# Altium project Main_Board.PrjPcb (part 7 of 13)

## Sheet RAM_Power.SchDoc: RAM_POWER
size A3; Organization: Altium Limited; Address1: L3, 12a Rodborough Rd; Address2: Frenchs Forest; Address3: NSW; Address4: Australia 2086
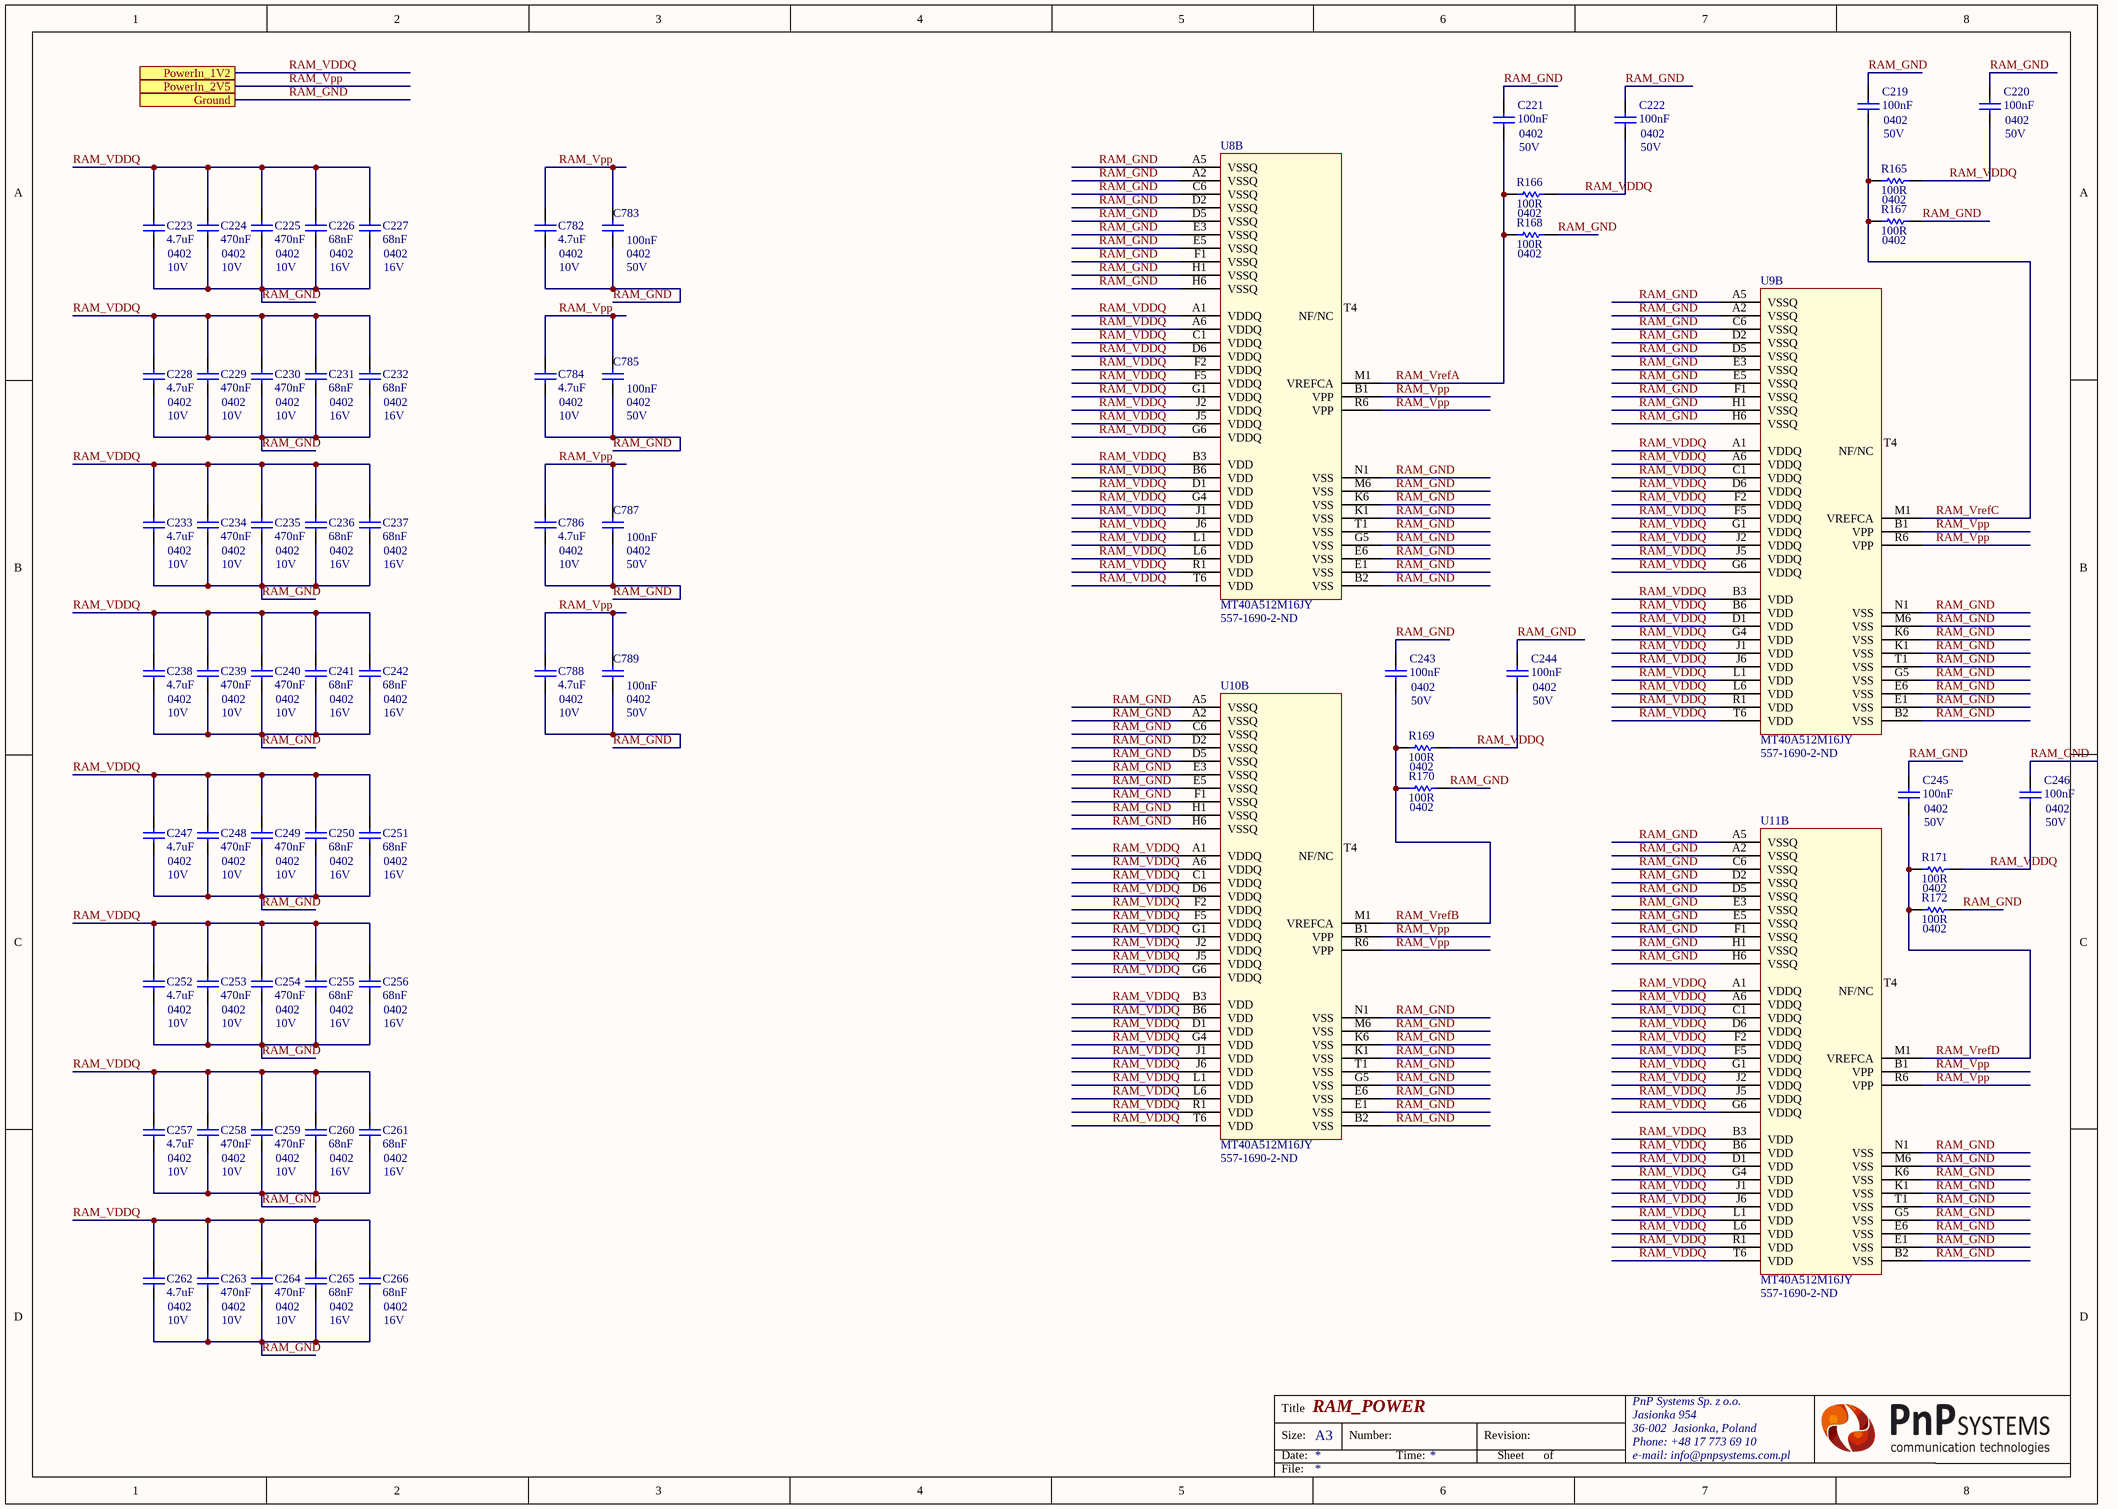
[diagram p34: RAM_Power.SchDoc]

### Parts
C219  100nF  Case Code (Imperial): 0402  Voltage: 50V  [CAP 0402/1005 KK]
C220  100nF  Case Code (Imperial): 0402  Voltage: 50V  [CAP 0402/1005 KK]
C221  100nF  Case Code (Imperial): 0402  Voltage: 50V  [CAP 0402/1005 KK]
C222  100nF  Case Code (Imperial): 0402  Voltage: 50V  [CAP 0402/1005 KK]
C223  4.7uF  Case/Package: 0402  Voltage Rating: 10V  [CAP 0402/1005 KK]
C224  470nF  Case/Package: 0402  Voltage Rating: 10V  [CAP 0402/1005 KK]
C225  470nF  Case/Package: 0402  Voltage Rating: 10V  [CAP 0402/1005 KK]
C226  68nF  Case/Package: 0402  Voltage Rating (DC): 16V  [CAP 0402/1005 KK]
C227  68nF  Case/Package: 0402  Voltage: 16V  [CAP 0402/1005 KK]
C228  4.7uF  Case/Package: 0402  Voltage Rating: 10V  [CAP 0402/1005 KK]
C229  470nF  Case/Package: 0402  Voltage Rating: 10V  [CAP 0402/1005 KK]
C230  470nF  Case/Package: 0402  Voltage Rating: 10V  [CAP 0402/1005 KK]
C231  68nF  Case/Package: 0402  Voltage Rating (DC): 16V  [CAP 0402/1005 KK]
C232  68nF  Case/Package: 0402  Voltage: 16V  [CAP 0402/1005 KK]
C233  4.7uF  Case/Package: 0402  Voltage Rating: 10V  [CAP 0402/1005 KK]
C234  470nF  Case/Package: 0402  Voltage Rating: 10V  [CAP 0402/1005 KK]
C235  470nF  Case/Package: 0402  Voltage Rating: 10V  [CAP 0402/1005 KK]
C236  68nF  Case/Package: 0402  Voltage Rating (DC): 16V  [CAP 0402/1005 KK]
C237  68nF  Case/Package: 0402  Voltage: 16V  [CAP 0402/1005 KK]
C238  4.7uF  Case/Package: 0402  Voltage Rating: 10V  [CAP 0402/1005 KK]
C239  470nF  Case/Package: 0402  Voltage Rating: 10V  [CAP 0402/1005 KK]
C240  470nF  Case/Package: 0402  Voltage Rating: 10V  [CAP 0402/1005 KK]
C241  68nF  Case/Package: 0402  Voltage Rating (DC): 16V  [CAP 0402/1005 KK]
C242  68nF  Case/Package: 0402  Voltage: 16V  [CAP 0402/1005 KK]
C243  100nF  Case Code (Imperial): 0402  Voltage: 50V  [CAP 0402/1005 KK]
C244  100nF  Case Code (Imperial): 0402  Voltage: 50V  [CAP 0402/1005 KK]
C245  100nF  Case Code (Imperial): 0402  Voltage: 50V  [CAP 0402/1005 KK]
C246  100nF  Case Code (Imperial): 0402  Voltage: 50V  [CAP 0402/1005 KK]
C247  4.7uF  Case/Package: 0402  Voltage Rating: 10V  [CAP 0402/1005 KK]
C248  470nF  Case/Package: 0402  Voltage Rating: 10V  [CAP 0402/1005 KK]
C249  470nF  Case/Package: 0402  Voltage Rating: 10V  [CAP 0402/1005 KK]
C250  68nF  Case/Package: 0402  Voltage Rating (DC): 16V  [CAP 0402/1005 KK]
C251  68nF  Case/Package: 0402  Voltage: 16V  [CAP 0402/1005 KK]
C252  4.7uF  Case/Package: 0402  Voltage Rating: 10V  [CAP 0402/1005 KK]
C253  470nF  Case/Package: 0402  Voltage Rating: 10V  [CAP 0402/1005 KK]
C254  470nF  Case/Package: 0402  Voltage Rating: 10V  [CAP 0402/1005 KK]
C255  68nF  Case/Package: 0402  Voltage Rating (DC): 16V  [CAP 0402/1005 KK]
C256  68nF  Case/Package: 0402  Voltage: 16V  [CAP 0402/1005 KK]
C257  4.7uF  Case/Package: 0402  Voltage Rating: 10V  [CAP 0402/1005 KK]
C258  470nF  Case/Package: 0402  Voltage Rating: 10V  [CAP 0402/1005 KK]
C259  470nF  Case/Package: 0402  Voltage Rating: 10V  [CAP 0402/1005 KK]
C260  68nF  Case/Package: 0402  Voltage Rating (DC): 16V  [CAP 0402/1005 KK]
C261  68nF  Case/Package: 0402  Voltage: 16V  [CAP 0402/1005 KK]
C262  4.7uF  Case/Package: 0402  Voltage Rating: 10V  [CAP 0402/1005 KK]
C263  470nF  Case/Package: 0402  Voltage Rating: 10V  [CAP 0402/1005 KK]
C264  470nF  Case/Package: 0402  Voltage Rating: 10V  [CAP 0402/1005 KK]
C265  68nF  Case/Package: 0402  Voltage Rating (DC): 16V  [CAP 0402/1005 KK]
C266  68nF  Case/Package: 0402  Voltage: 16V  [CAP 0402/1005 KK]
C782  4.7uF  Case/Package: 0402  Voltage Rating: 10V  [CAP 0402/1005 KK]
C783  100nF  Case Code (Imperial): 0402  Voltage: 50V  [CAP 0402/1005 KK]
C784  4.7uF  Case/Package: 0402  Voltage Rating: 10V  [CAP 0402/1005 KK]
C785  100nF  Case Code (Imperial): 0402  Voltage: 50V  [CAP 0402/1005 KK]
C786  4.7uF  Case/Package: 0402  Voltage Rating: 10V  [CAP 0402/1005 KK]
C787  100nF  Case Code (Imperial): 0402  Voltage: 50V  [CAP 0402/1005 KK]
C788  4.7uF  Case/Package: 0402  Voltage Rating: 10V  [CAP 0402/1005 KK]
C789  100nF  Case Code (Imperial): 0402  Voltage: 50V  [CAP 0402/1005 KK]
R165  100R  Case/Package: 0402  [RES 0402/1005 RF KK]
R166  100R  Case/Package: 0402  [RES 0402/1005 RF KK]
R167  100R  Case/Package: 0402  [RES 0402/1005 RF KK]
R168  100R  Case/Package: 0402  [RES 0402/1005 RF KK]
R169  100R  Case/Package: 0402  [RES 0402/1005 RF KK]
R170  100R  Case/Package: 0402  [RES 0402/1005 RF KK]
R171  100R  Case/Package: 0402  [RES 0402/1005 RF KK]
R172  100R  Case/Package: 0402  [RES 0402/1005 RF KK]
U8  MT40A512M16JY  Supplier Part Number 1: 557-1690-2-ND  [MT40A512M16JY]  (part B of 2)
U9  MT40A512M16JY  Supplier Part Number 1: 557-1690-2-ND  [MT40A512M16JY]  (part B of 2)
U10  MT40A512M16JY  Supplier Part Number 1: 557-1690-2-ND  [MT40A512M16JY]  (part B of 2)
U11  MT40A512M16JY  Supplier Part Number 1: 557-1690-2-ND  [MT40A512M16JY]  (part B of 2)

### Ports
Ground, PowerIn_1V2, PowerIn_2V5

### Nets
RAM_GND: C219.2 C220.2 C221.2 C222.2 C223.1 C224.1 C225.1 C226.1 C227.1 C228.1 C229.1 C230.1 C231.1 C232.1 C233.1 C234.1 C235.1 C236.1 C237.1 C238.1 C239.1 C240.1 C241.1 C242.1 C243.2 C244.2 C245.2 C246.2 C247.1 C248.1 C249.1 C250.1 C251.1 C252.1 C253.1 C254.1 C255.1 C256.1 C257.1 C258.1 C259.1 C260.1 C261.1 C262.1 C263.1 C264.1 C265.1 C266.1 C782.1 C783.1 C784.1 C785.1 C786.1 C787.1 C788.1 C789.1 R167.2 R168.2 R170.2 R172.2 U8.A2(VSSQ) U8.A5(VSSQ) U8.B2(VSS) U8.C6(VSSQ) U8.D2(VSSQ) U8.D5(VSSQ) U8.E1(VSS) U8.E3(VSSQ) U8.E5(VSSQ) U8.E6(VSS) U8.F1(VSSQ) U8.G5(VSS) U8.H1(VSSQ) U8.H6(VSSQ) U8.K1(VSS) U8.K6(VSS) U8.M6(VSS) U8.N1(VSS) U8.T1(VSS) U9.A2(VSSQ) U9.A5(VSSQ) U9.B2(VSS) U9.C6(VSSQ) U9.D2(VSSQ) U9.D5(VSSQ) U9.E1(VSS) U9.E3(VSSQ) U9.E5(VSSQ) U9.E6(VSS) U9.F1(VSSQ) U9.G5(VSS) U9.H1(VSSQ) U9.H6(VSSQ) U9.K1(VSS) U9.K6(VSS) U9.M6(VSS) U9.N1(VSS) U9.T1(VSS) U10.A2(VSSQ) U10.A5(VSSQ) U10.B2(VSS) U10.C6(VSSQ) U10.D2(VSSQ) U10.D5(VSSQ) U10.E1(VSS) U10.E3(VSSQ) U10.E5(VSSQ) U10.E6(VSS) U10.F1(VSSQ) U10.G5(VSS) U10.H1(VSSQ) U10.H6(VSSQ) U10.K1(VSS) U10.K6(VSS) U10.M6(VSS) U10.N1(VSS) U10.T1(VSS) U11.A2(VSSQ) U11.A5(VSSQ) U11.B2(VSS) U11.C6(VSSQ) U11.D2(VSSQ) U11.D5(VSSQ) U11.E1(VSS) U11.E3(VSSQ) U11.E5(VSSQ) U11.E6(VSS) U11.F1(VSSQ) U11.G5(VSS) U11.H1(VSSQ) U11.H6(VSSQ) U11.K1(VSS) U11.K6(VSS) U11.M6(VSS) U11.N1(VSS) U11.T1(VSS) ; port Ground  [project net B503_Ground]
RAM_VDDQ: C220.1 C222.1 C223.2 C224.2 C225.2 C226.2 C227.2 C228.2 C229.2 C230.2 C231.2 C232.2 C233.2 C234.2 C235.2 C236.2 C237.2 C238.2 C239.2 C240.2 C241.2 C242.2 C244.1 C246.1 C247.2 C248.2 C249.2 C250.2 C251.2 C252.2 C253.2 C254.2 C255.2 C256.2 C257.2 C258.2 C259.2 C260.2 C261.2 C262.2 C263.2 C264.2 C265.2 C266.2 R165.2 R166.2 R169.2 R171.2 U8.A1(VDDQ) U8.A6(VDDQ) U8.B3(VDD) U8.B6(VDD) U8.C1(VDDQ) U8.D1(VDD) U8.D6(VDDQ) U8.F2(VDDQ) U8.F5(VDDQ) U8.G1(VDDQ) U8.G4(VDD) U8.G6(VDDQ) U8.J1(VDD) U8.J2(VDDQ) U8.J5(VDDQ) U8.J6(VDD) U8.L1(VDD) U8.L6(VDD) U8.R1(VDD) U8.T6(VDD) U9.A1(VDDQ) U9.A6(VDDQ) U9.B3(VDD) U9.B6(VDD) U9.C1(VDDQ) U9.D1(VDD) U9.D6(VDDQ) U9.F2(VDDQ) U9.F5(VDDQ) U9.G1(VDDQ) U9.G4(VDD) U9.G6(VDDQ) U9.J1(VDD) U9.J2(VDDQ) U9.J5(VDDQ) U9.J6(VDD) U9.L1(VDD) U9.L6(VDD) U9.R1(VDD) U9.T6(VDD) U10.A1(VDDQ) U10.A6(VDDQ) U10.B3(VDD) U10.B6(VDD) U10.C1(VDDQ) U10.D1(VDD) U10.D6(VDDQ) U10.F2(VDDQ) U10.F5(VDDQ) U10.G1(VDDQ) U10.G4(VDD) U10.G6(VDDQ) U10.J1(VDD) U10.J2(VDDQ) U10.J5(VDDQ) U10.J6(VDD) U10.L1(VDD) U10.L6(VDD) U10.R1(VDD) U10.T6(VDD) U11.A1(VDDQ) U11.A6(VDDQ) U11.B3(VDD) U11.B6(VDD) U11.C1(VDDQ) U11.D1(VDD) U11.D6(VDDQ) U11.F2(VDDQ) U11.F5(VDDQ) U11.G1(VDDQ) U11.G4(VDD) U11.G6(VDDQ) U11.J1(VDD) U11.J2(VDDQ) U11.J5(VDDQ) U11.J6(VDD) U11.L1(VDD) U11.L6(VDD) U11.R1(VDD) U11.T6(VDD) ; port PowerIn_1V2  [project net RAM_Vcc1V2]
RAM_Vpp: C782.2 C783.2 C784.2 C785.2 C786.2 C787.2 C788.2 C789.2 U8.B1(VPP) U8.R6(VPP) U9.B1(VPP) U9.R6(VPP) U10.B1(VPP) U10.R6(VPP) U11.B1(VPP) U11.R6(VPP) ; port PowerIn_2V5  [project net 2V5@1.5A]
RAM_VrefA: C221.1 R166.1 R168.1 U8.M1(VREFCA)
RAM_VrefB: C243.1 R169.1 R170.1 U10.M1(VREFCA)
RAM_VrefC: C219.1 R165.1 R167.1 U9.M1(VREFCA)
RAM_VrefD: C245.1 R171.1 R172.1 U11.M1(VREFCA)

Not connected (* = marked no-connect by the designer): U8 T4(NF/NC); U9 T4(NF/NC); U10 T4(NF/NC); U11 T4(NF/NC)

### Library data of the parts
C219-C222 C243-C246 C783 C785 C787 C789 = Capacitor: CAP CER 0.1UF 50V X5R 0402; Manufacturer: Murata; Manufacturer Part Number: GRM155R61H104KE14D; Dielectric Material: Ceramic; Dissipation Factor: 0.025%; Tolerance: 10%
C223 C228 C233 C238 C247 C252 C257 C262 C782 C784 C786 C788 = Capacitor: 0402 10 V 4.7 uF ±20% Tolerance X5R Multilayer Ceramic Chip Capacitor; Manufacturer: Murata; Manufacturer Part Number: GRM155R61A475MEAAD
C224 C225 C229 C230 C234 C235 C239 C240 C248 C249 C253 C254 C258 C259 C263 C264 = Capacitor: Cap Ceramic 0.47uF 10V X5R 10% SMD 0402 85C Paper T/R; Manufacturer: Samsung; Manufacturer Part Number: CL05A474KP5NNNC
C226 C227 C231 C232 C236 C237 C241 C242 C250 C251 C255 C256 C260 C261 C265 C266 = Capacitor: KEMET - C0402C683K4RACTU - CAP, 0.068µF, 16V, 10%, X7R, 0402; Dielectric Material: Ceramic; Dissipation Factor: 3.5%
R165-R172 = Resistor: RES SMD 100 OHM 1% 1/16W 0402; Manufacturer: Yageo; Manufacturer Part Number: RC0402FR-07100RL; Power Rating: 62.5mW; Voltage Rating: 50V; Temperature Coefficient: 100ppm/°C
U8-U11 = MT40A512M16JY: RAM 8GB; Manufacturer: Micron Technology; Manufacturer Part Number: MT40A512M16JY-083EIT:BTR; Memory Type: RAM,SDRAM; Frequency: 1.2GHz; Interface: Parallel

## Sheet XilinxPower.SchDoc
size A3; Organization: Altium Limited; Address1: L3, 12a Rodborough Rd; Address2: Frenchs Forest; Address3: NSW; Address4: Australia 2086
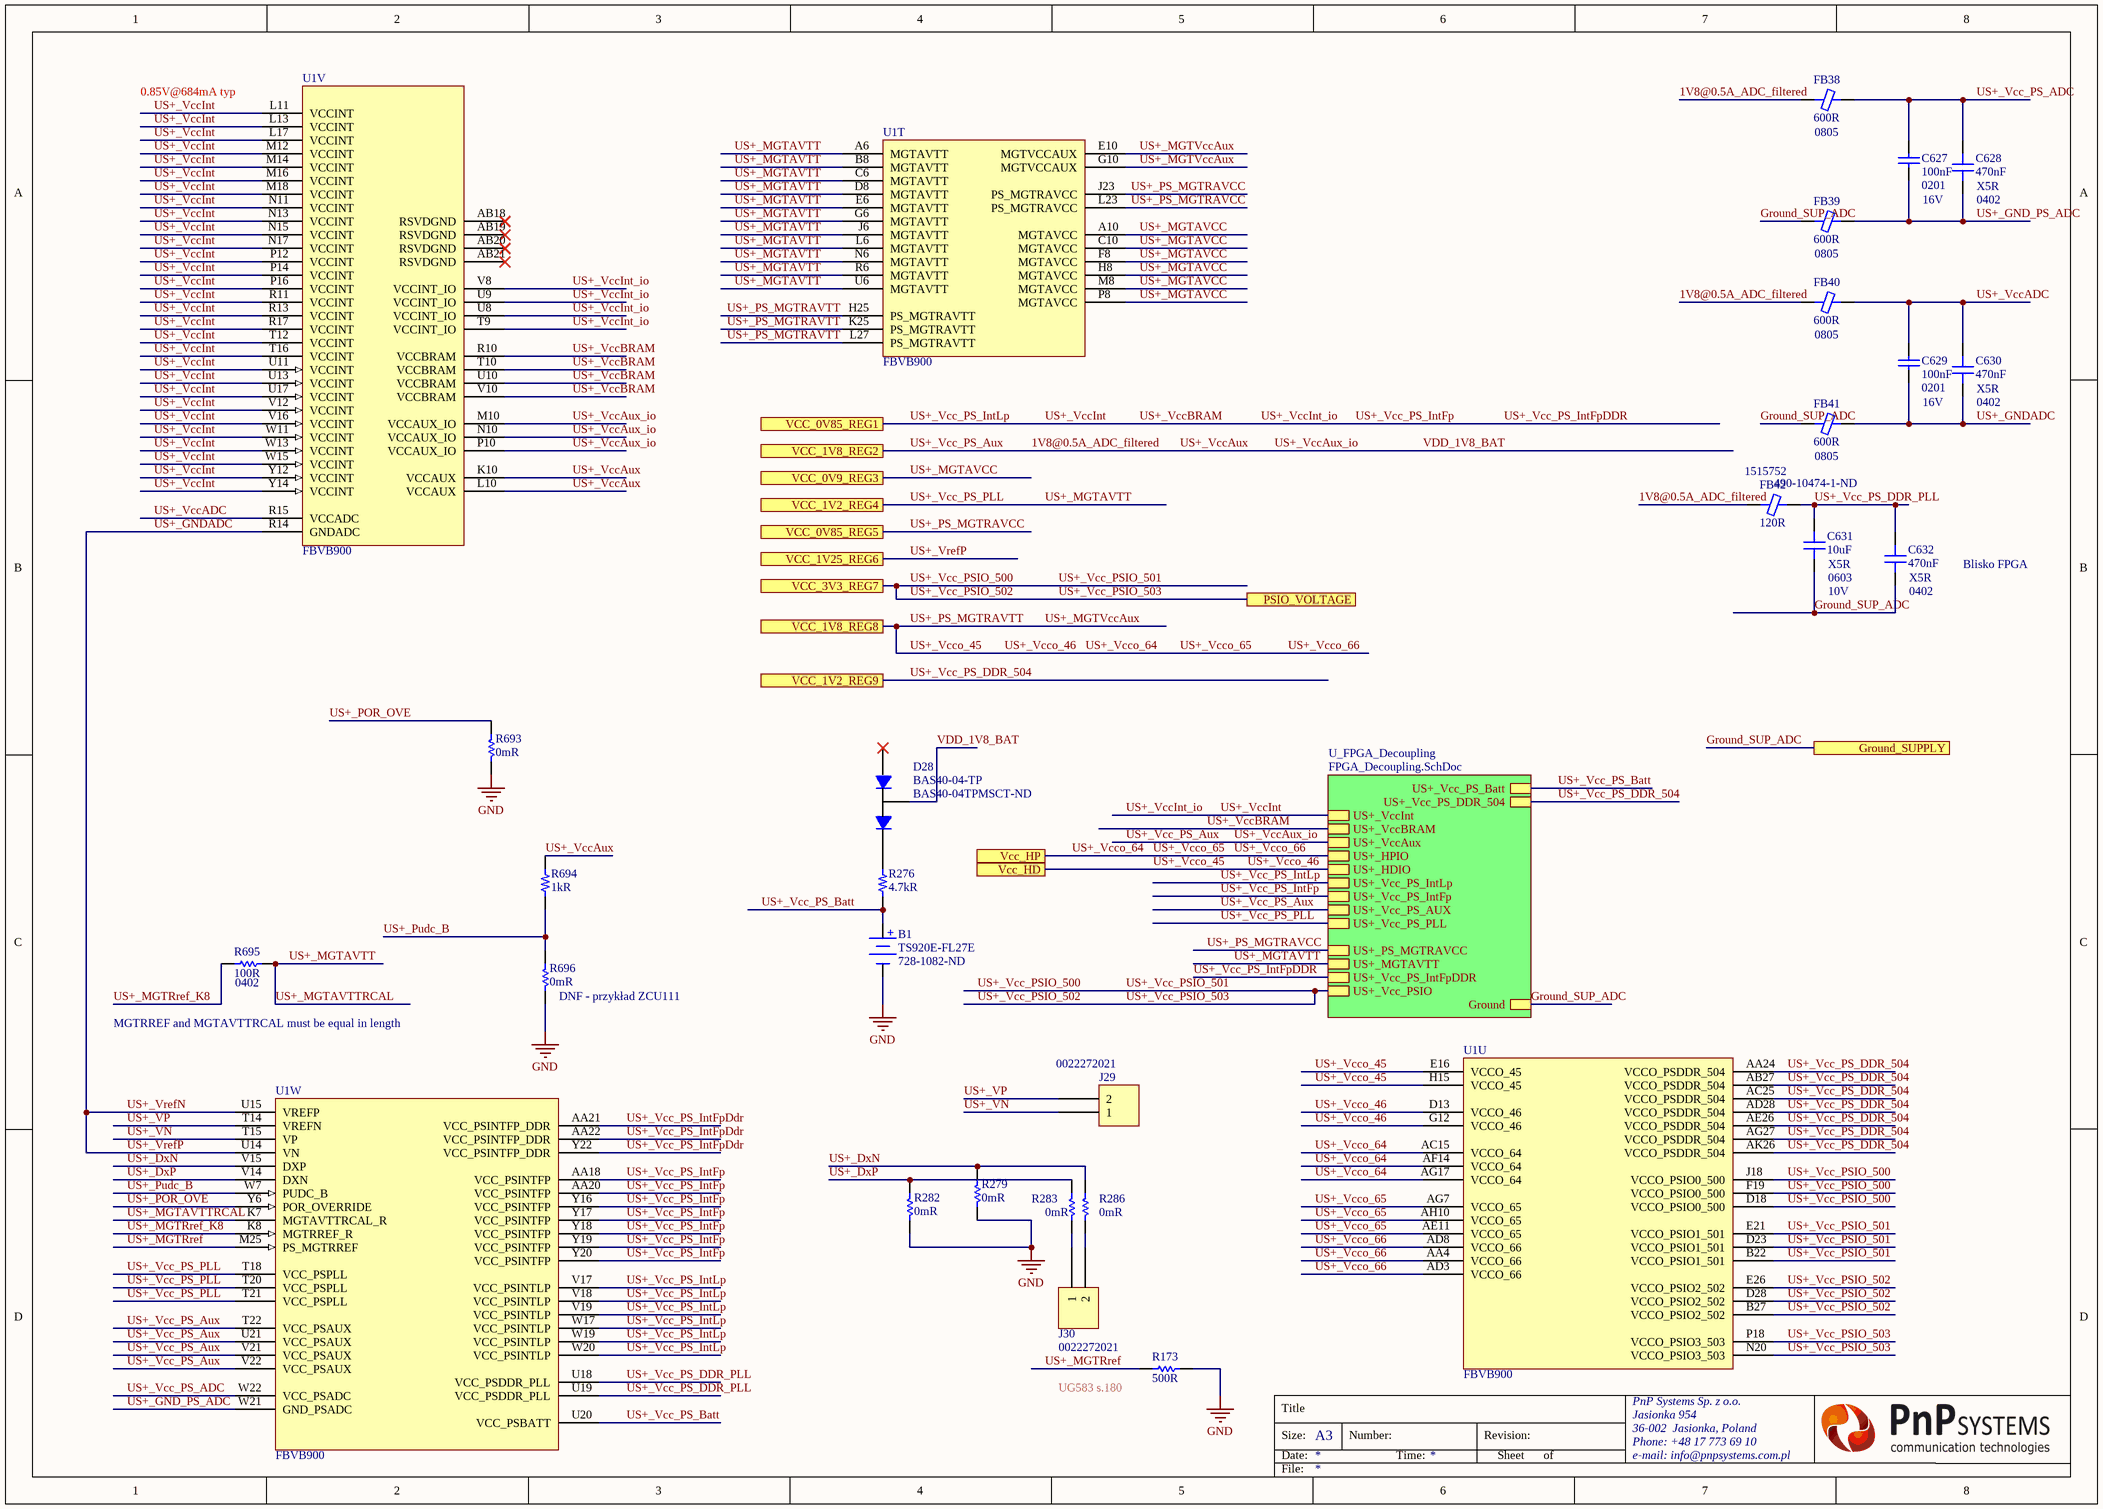
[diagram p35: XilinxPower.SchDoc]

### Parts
B1  TS920E-FL27E  Supplier Part Number 1: 728-1082-ND  [Battery]
C627  100nF  Case/Package: 0201  Voltage Rating: 16V  [CAP 0201/0603 KK]
C628  470nF  Case/Package: 0402  Dielectric: X5R  [CAP 0402/1005 KK]
C629  100nF  Case/Package: 0201  Voltage Rating: 16V  [CAP 0201/0603 KK]
C630  470nF  Case/Package: 0402  Dielectric: X5R  [CAP 0402/1005 KK]
C631  10uF  Supplier Part Number 1: 490-10474-1-ND  Case/Package: 0603  Dielectric: X5R  Voltage Rating: 10V  [CAP 0603/1608 RF]
C632  470nF  Case/Package: 0402  Dielectric: X5R  [CAP 0402/1005 KK]
D28  BAS40-04-TP  Supplier Part Number 1: BAS40-04TPMSCT-ND  [BAS40-04-TP]
FB38  600R  Case/Package: 0805  [FER 0805/2012]
FB39  600R  Case/Package: 0805  [FER 0805/2012]
FB40  600R  Case/Package: 0805  [FER 0805/2012]
FB41  600R  Case/Package: 0805  [FER 0805/2012]
FB42  120R  Supplier Part Number 1: 1515752  [FER 0603/1608]
J29  Supplier Part Number 1: 0022272021  [MOLEX KK 0022272021]  (hidden comment: SYSMON_VP_VN)
J30  Supplier Part Number 1: 0022272021  [MOLEX KK 0022272021]  (hidden comment: SYSMON_VP_VN)
R173  500R  [RES 0402/1005 RF KK]
R276  4.7kR  [RES 0402/1005 RF KK]
R279  0mR  [RES 0402/1005 RF KK]
R282  0mR  [RES 0402/1005 RF KK]
R283  0mR  [RES 0402/1005 RF KK]
R286  0mR  [RES 0402/1005 RF KK]
R693  0mR  [RES 0402/1005 RF KK]
R694  1kR  [RES 0402/1005 RF KK]
R695  100R  Case/Package: 0402  [RES 0402/1005 RF KK]
R696  0mR  [RES 0402/1005 RF KK]
U1  FBVB900  [FBVB900 XX]  (parts T,U,V,W of 23)

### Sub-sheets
U_FPGA_Decoupling = FPGA_Decoupling.SchDoc: US+_VccInt, US+_VccBRAM, Ground, US+_VccAux, US+_HPIO, US+_HDIO, US+_Vcc_PS_IntLp, US+_PS_MGTRAVCC, US+_MGTAVTT, US+_Vcc_PS_IntFp, US+_Vcc_PS_AUX, US+_Vcc_PS_PLL, US+_Vcc_PSIO, US+_Vcc_PS_Batt, US+_Vcc_PS_DDR_504, US+_Vcc_PS_IntFpDDR

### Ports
Ground_SUPPLY, PSIO_VOLTAGE, VCC_0V9_REG3, VCC_0V85_REG1, VCC_0V85_REG5, VCC_1V2_REG4, VCC_1V2_REG9, VCC_1V8_REG2, VCC_1V8_REG8, VCC_1V25_REG6, VCC_3V3_REG7, Vcc_HD, Vcc_HP

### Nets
GND: B1.2(-) C631.1 C632.1 FB39.1 FB41.1 R173.2 R279.2 R282.2 R693.2 R696.2 ; port Ground_SUPPLY, sheet U_FPGA_Decoupling/Ground  [also labelled Ground_SUP_ADC]  [project net B503_Ground]
1V8@0.5A_ADC_filtered: D28.3 FB38.1 FB40.1 FB42.1 R694.1 U1.K10(VCCAUX) U1.L10(VCCAUX) U1.M10(VCCAUX_IO) U1.N10(VCCAUX_IO) U1.P10(VCCAUX_IO) U1.T22(VCC_PSAUX) U1.U21(VCC_PSAUX) U1.V21(VCC_PSAUX) U1.V22(VCC_PSAUX) ; port VCC_1V8_REG2, sheet U_FPGA_Decoupling/US+_VccAux, sheet U_FPGA_Decoupling/US+_Vcc_PS_AUX  [also labelled US+_Vcc_PS_Aux, US+_VccAux, US+_VccAux_io, VDD_1V8_BAT]
US+_DxN: R279.1 R286.1 U1.V15(DXP)
US+_DxP: R282.1 R283.1 U1.V14(DXN)
US+_GND_PS_ADC: C627.1 C628.1 FB39.2 U1.W21(GND_PSADC)
US+_GNDADC: C629.1 C630.1 FB41.2 U1.R14(GNDADC) U1.U14(VN) U1.U15(VREFP) ; port VCC_1V25_REG6  [also labelled US+_VrefN, US+_VrefP]
US+_MGTAVCC: U1.A10(MGTAVCC) U1.C10(MGTAVCC) U1.F8(MGTAVCC) U1.H8(MGTAVCC) U1.M8(MGTAVCC) U1.P8(MGTAVCC) ; port VCC_0V9_REG3  [project net 0V9@1A_REG3]
US+_MGTAVTT: R695.2 U1.A6(MGTAVTT) U1.B8(MGTAVTT) U1.C6(MGTAVTT) U1.D8(MGTAVTT) U1.E6(MGTAVTT) U1.G6(MGTAVTT) U1.J6(MGTAVTT) U1.K7(MGTAVTTRCAL_R) U1.L6(MGTAVTT) U1.N6(MGTAVTT) U1.R6(MGTAVTT) U1.T18(VCC_PSPLL) U1.T20(VCC_PSPLL) U1.T21(VCC_PSPLL) U1.U6(MGTAVTT) ; port VCC_1V2_REG4, sheet U_FPGA_Decoupling/US+_MGTAVTT, sheet U_FPGA_Decoupling/US+_Vcc_PS_PLL  [also labelled US+_MGTAVTTRCAL, US+_Vcc_PS_PLL]  [project net RAM_Vcc1V2]
US+_MGTRref: R173.1 U1.M25(PS_MGTRREF)
US+_MGTRref_K8: R695.1 U1.K8(MGTRREF_R)
US+_MGTVccAux: U1.AA4(VCCO_66) U1.AC15(VCCO_64) U1.AD3(VCCO_66) U1.AD8(VCCO_66) U1.AE11(VCCO_65) U1.AF14(VCCO_64) U1.AG7(VCCO_65) U1.AG17(VCCO_64) U1.AH10(VCCO_65) U1.D13(VCCO_46) U1.E10(MGTVCCAUX) U1.E16(VCCO_45) U1.G10(MGTVCCAUX) U1.G12(VCCO_46) U1.H15(VCCO_45) U1.H25(PS_MGTRAVTT) U1.K25(PS_MGTRAVTT) U1.L27(PS_MGTRAVTT) ; port VCC_1V8_REG8, port Vcc_HP, port Vcc_HD, sheet U_FPGA_Decoupling/US+_HPIO, sheet U_FPGA_Decoupling/US+_HDIO  [also labelled US+_PS_MGTRAVTT, US+_Vcco_45, US+_Vcco_46, US+_Vcco_64, US+_Vcco_65, US+_Vcco_66]
US+_POR_OVE: R693.1 U1.Y6(POR_OVERRIDE)
US+_PS_MGTRAVCC: U1.J23(PS_MGTRAVCC) U1.L23(PS_MGTRAVCC) ; port VCC_0V85_REG5, sheet U_FPGA_Decoupling/US+_PS_MGTRAVCC  [project net 0V85@2A]
US+_Pudc_B: R694.2 R696.1 U1.W7(PUDC_B)
US+_Vcc_PS_ADC: C627.2 C628.2 FB38.2 U1.W22(VCC_PSADC)
US+_Vcc_PS_Batt: B1.1(+) R276.1 U1.U20(VCC_PSBATT) ; sheet U_FPGA_Decoupling/US+_Vcc_PS_Batt
US+_Vcc_PS_DDR_504: U1.AA24(VCCO_PSDDR_504) U1.AB27(VCCO_PSDDR_504) U1.AC25(VCCO_PSDDR_504) U1.AD28(VCCO_PSDDR_504) U1.AE26(VCCO_PSDDR_504) U1.AG27(VCCO_PSDDR_504) U1.AK26(VCCO_PSDDR_504) ; port VCC_1V2_REG9, sheet U_FPGA_Decoupling/US+_Vcc_PS_DDR_504
US+_Vcc_PS_DDR_PLL: C631.2 C632.2 FB42.2 U1.U18(VCC_PSDDR_PLL) U1.U19(VCC_PSDDR_PLL)
US+_Vcc_PS_IntFp: U1.AA18(VCC_PSINTFP) U1.AA20(VCC_PSINTFP) U1.AA21(VCC_PSINTFP_DDR) U1.AA22(VCC_PSINTFP_DDR) U1.L11(VCCINT) U1.L13(VCCINT) U1.L17(VCCINT) U1.M12(VCCINT) U1.M14(VCCINT) U1.M16(VCCINT) U1.M18(VCCINT) U1.N11(VCCINT) U1.N13(VCCINT) U1.N15(VCCINT) U1.N17(VCCINT) U1.P12(VCCINT) U1.P14(VCCINT) U1.P16(VCCINT) U1.R10(VCCBRAM) U1.R11(VCCINT) U1.R13(VCCINT) U1.R17(VCCINT) U1.T9(VCCINT_IO) U1.T10(VCCBRAM) U1.T12(VCCINT) U1.T16(VCCINT) U1.U8(VCCINT_IO) U1.U9(VCCINT_IO) U1.U10(VCCBRAM) U1.U11(VCCINT) U1.U13(VCCINT) U1.U17(VCCINT) U1.V8(VCCINT_IO) U1.V10(VCCBRAM) U1.V12(VCCINT) U1.V16(VCCINT) U1.V17(VCC_PSINTLP) U1.V18(VCC_PSINTLP) U1.V19(VCC_PSINTLP) U1.W11(VCCINT) U1.W13(VCCINT) U1.W15(VCCINT) U1.W17(VCC_PSINTLP) U1.W19(VCC_PSINTLP) U1.W20(VCC_PSINTLP) U1.Y12(VCCINT) U1.Y14(VCCINT) U1.Y16(VCC_PSINTFP) U1.Y17(VCC_PSINTFP) U1.Y18(VCC_PSINTFP) U1.Y19(VCC_PSINTFP) U1.Y20(VCC_PSINTFP) U1.Y22(VCC_PSINTFP_DDR) ; port VCC_0V85_REG1, sheet U_FPGA_Decoupling/US+_VccInt, sheet U_FPGA_Decoupling/US+_VccBRAM, sheet U_FPGA_Decoupling/US+_Vcc_PS_IntLp, sheet U_FPGA_Decoupling/US+_Vcc_PS_IntFp, sheet U_FPGA_Decoupling/US+_Vcc_PS_IntFpDDR  [also labelled US+_Vcc_PS_IntFpDdr, US+_Vcc_PS_IntLp, US+_VccBRAM, US+_VccInt, US+_VccInt_io]
US+_Vcc_PSIO_500: U1.B22(VCCO_PSIO1_501) U1.B27(VCCO_PSIO2_502) U1.D18(VCCO_PSIO0_500) U1.D23(VCCO_PSIO1_501) U1.D28(VCCO_PSIO2_502) U1.E21(VCCO_PSIO1_501) U1.E26(VCCO_PSIO2_502) U1.F19(VCCO_PSIO0_500) U1.J18(VCCO_PSIO0_500) U1.N20(VCCO_PSIO3_503) U1.P18(VCCO_PSIO3_503) ; port PSIO_VOLTAGE, port VCC_3V3_REG7, sheet U_FPGA_Decoupling/US+_Vcc_PSIO  [also labelled US+_Vcc_PSIO_501, US+_Vcc_PSIO_502, US+_Vcc_PSIO_503]  [project net ETH_VDDIO]
US+_VccADC: C629.2 C630.2 FB40.2 U1.R15(VCCADC)
US+_VN: J29.1 U1.T15(VP)
US+_VP: J29.2 U1.T14(VREFN)
NetD28_2: D28.2(K) R276.2
NetJ30_1: J30.1 R283.2
NetJ30_2: J30.2 R286.2

Not connected (* = marked no-connect by the designer): D28 1(A)*; U1 AB18(RSVDGND)* AB19(RSVDGND)* AB20(RSVDGND)* AB21(RSVDGND)*

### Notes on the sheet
- 0.85V@684mA typ
- Blisko FPGA
- MGTRREF and MGTAVTTRCAL must be equal in length
- (near R696) DNF - przykład ZCU111
- (near R173) UG583 s.180

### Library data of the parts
B1 = TS920E-FL27E: BATT LITH 1.5V 5.5MAH COIN 9.5MM; Manufacturer: Seiko
C627 C629 = Capacitor: CAP CER 0.1UF 16V X5R 0201; Manufacturer: Murata; Manufacturer Part Number: GRM033R61C104ME84D; Tolerance: 20%
C628 C630 C632 = Capacitor: Manufacturer: Samsung; Manufacturer Part Number: CL05A474KP5NNNC; Tolerance: 10%; Voltage Rating: 10V
C631 = Capacitor: Manufacturer: Murata; Manufacturer Part Number: GRM188R61A106KE69D; Tolerance: 10%
D28 = BAS40-04-TP: DIODE ARRAY SCHOTTKY 40V SOT23; Manufacturer: MCC; Max Surge Current: 600mA; Recovery Time: 5ns; Forward Current: 200mA; Forward Voltage: 1V; Max Reverse Leakage Current: 200nA; Power Dissipation: 200mW; Capacitance: 5pF; Element Configuration: Single
FB38-FB41 = Ferrite: FERRITE BEAD 600 OHM 0805 1LN; Manufacturer: Laird; Manufacturer Part Number: HZ0805E601R-10; Current Rating: 500mA; Number of Lines: 1; DC Resistance (DCR): 300mR; Test Frequency: 100MHz
FB42 = Ferrite: Ind Chip Bead 120Ohm 25% 100MHz Ferrite 3A 0603 Paper T/R; Manufacturer: Murata; Manufacturer Part Number: BLM18SG121TN1D; Material: Steel,Ferrite; DC Resistance (DCR): 25mR; Number of Circuits: 1; Shielding: Unshielded
J29 J30 = 2 Pin: Manufacturer: Molex; Number of Positions: 2; Contact Resistance: 20mR; Current Rating: 4A; Voltage Rating: 250V; Gender: Male; Insulation Resistance: 50GR; Pitch: 2.54mm; Approvals: UL,CSA
R173 = Resistor: RES SMD 500 OHM 0.1% 1/20W 0402; Manufacturer: Vishay Dale; Manufacturer Part Number: PNM0402E5000BST1; Max Power Dissipation: 50mW; Temperature Coefficient: 25ppm/°C
R276 = Resistor: Manufacturer: Panasonic; Manufacturer Part Number: ERJ-2RKF4701X; Tolerance: 1%; Temperature Coefficient: 100ppm/°C; Power Rating: 100mW; Voltage Rating: 50V
R279 R282 R283 R286 R693 R696 = Resistor: Manufacturer 1: Yageo; Manufacturer Part Number 1: RC0402JR-070RL; Power Rating: 62.5mW; Tolerance: 5%; Voltage Rating: 50V; Max Power Dissipation: 63mW; Temperature Coefficient: 200ppm/°C
R694 = Resistor: Manufacturer: Panasonic; Manufacturer Part Number: ERJ-2RKF1001X; Tolerance: 1%; Power Rating: 100mW; Temperature Coefficient: 100ppm/°C; Voltage Rating: 50V
R695 = Resistor: as R165-R172 on sheet RAM_Power
U1 = FBVB900: FPGA Zynq UltraScale+ Family 192150 Cells 20nm Technology 0.85V 900-Pin FCBGA Tray; Manufacturer Part Number: XCZU4CG-1FBVB900E; Manufacturer: Xilinx; Peripherals: WDT,DMA; Interface: I2C,SPI,USB,Ethernet,MMC,SDIO,SD,UART,USART,EBI/EMI; Core Architecture: ARM; RAM Size: 256KB; Frequency: 500MHz; Number of I/Os: 204

## Sheet FPGA_Decoupling.SchDoc
size A4
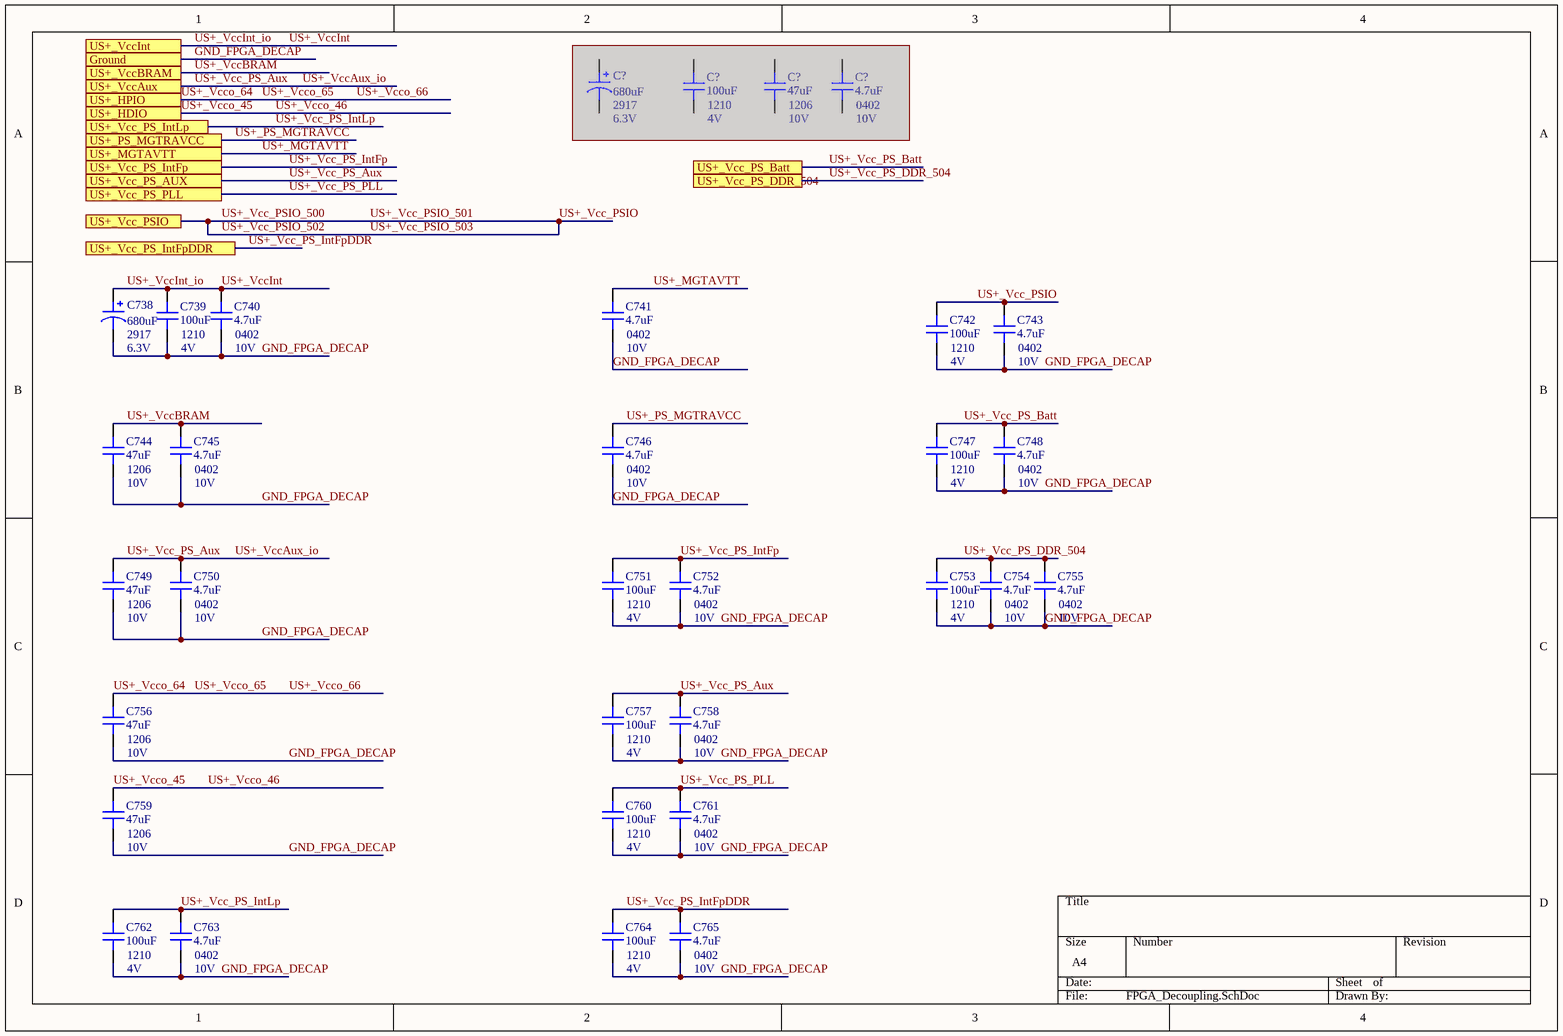
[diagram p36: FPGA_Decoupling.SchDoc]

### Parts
(Parts that share a designator on the sheet are numbered #1, #2 ... from top to bottom, then left to right.)
C738  Case/Package: 2917  Capacitance: 680uF  Voltage: 6.3V  [CAP POL 2917/7343]  (hidden comment: 6TPE680MI)
C739  100uF  Case Code (Imperial): 1210  Voltage Rating: 4V  [CAP 1210/3225 - 1MM]
C740  4.7uF  Case/Package: 0402  Voltage Rating: 10V  [CAP 0402/1005 KK]
C741  4.7uF  Case/Package: 0402  Voltage Rating: 10V  [CAP 0402/1005 KK]
C742  100uF  Case Code (Imperial): 1210  Voltage Rating: 4V  [CAP 1210/3225 - 1MM]
C743  4.7uF  Case/Package: 0402  Voltage Rating: 10V  [CAP 0402/1005 KK]
C744  47uF  Case/Package: 1206  Voltage Rating: 10V  [CAP 1206/3216 - 0.8MM]
C745  4.7uF  Case/Package: 0402  Voltage Rating: 10V  [CAP 0402/1005 KK]
C746  4.7uF  Case/Package: 0402  Voltage Rating: 10V  [CAP 0402/1005 KK]
C747  100uF  Case Code (Imperial): 1210  Voltage Rating: 4V  [CAP 1210/3225 - 1MM]
C748  4.7uF  Case/Package: 0402  Voltage Rating: 10V  [CAP 0402/1005 KK]
C749  47uF  Case/Package: 1206  Voltage Rating: 10V  [CAP 1206/3216 - 0.8MM]
C750  4.7uF  Case/Package: 0402  Voltage Rating: 10V  [CAP 0402/1005 KK]
C751  100uF  Case Code (Imperial): 1210  Voltage Rating: 4V  [CAP 1210/3225 - 1MM]
C752  4.7uF  Case/Package: 0402  Voltage Rating: 10V  [CAP 0402/1005 KK]
C753  100uF  Case Code (Imperial): 1210  Voltage Rating: 4V  [CAP 1210/3225 - 1MM]
C754  4.7uF  Case/Package: 0402  Voltage Rating: 10V  [CAP 0402/1005 KK]
C755  4.7uF  Case/Package: 0402  Voltage Rating: 10V  [CAP 0402/1005 KK]
C756  47uF  Case/Package: 1206  Voltage Rating: 10V  [CAP 1206/3216 - 0.8MM]
C757  100uF  Case Code (Imperial): 1210  Voltage Rating: 4V  [CAP 1210/3225 - 1MM]
C758  4.7uF  Case/Package: 0402  Voltage Rating: 10V  [CAP 0402/1005 KK]
C759  47uF  Case/Package: 1206  Voltage Rating: 10V  [CAP 1206/3216 - 0.8MM]
C760  100uF  Case Code (Imperial): 1210  Voltage Rating: 4V  [CAP 1210/3225 - 1MM]
C761  4.7uF  Case/Package: 0402  Voltage Rating: 10V  [CAP 0402/1005 KK]
C762  100uF  Case Code (Imperial): 1210  Voltage Rating: 4V  [CAP 1210/3225 - 1MM]
C763  4.7uF  Case/Package: 0402  Voltage Rating: 10V  [CAP 0402/1005 KK]
C764  100uF  Case Code (Imperial): 1210  Voltage Rating: 4V  [CAP 1210/3225 - 1MM]
C765  4.7uF  Case/Package: 0402  Voltage Rating: 10V  [CAP 0402/1005 KK]
C?#1  Case/Package: 2917  Capacitance: 680uF  Voltage: 6.3V  [CAP POL 2917/7343]  (hidden comment: 6TPE680MI)  (masked out: inside a compile mask, not in the netlist)
C?#2  100uF  Case Code (Imperial): 1210  Voltage Rating: 4V  [CAP 1210/3225 - 1MM]  (masked out: inside a compile mask, not in the netlist)
C?#3  47uF  Case/Package: 1206  Voltage Rating: 10V  [CAP 1206/3216 - 0.8MM]  (masked out: inside a compile mask, not in the netlist)
C?#4  4.7uF  Case/Package: 0402  Voltage Rating: 10V  [CAP 0402/1005 KK]  (masked out: inside a compile mask, not in the netlist)

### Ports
Ground, US+_HDIO, US+_HPIO, US+_MGTAVTT, US+_PS_MGTRAVCC, US+_Vcc_PS_AUX, US+_Vcc_PS_Batt, US+_Vcc_PS_DDR_504, US+_Vcc_PS_IntFp, US+_Vcc_PS_IntFpDDR, US+_Vcc_PS_IntLp, US+_Vcc_PS_PLL, US+_Vcc_PSIO, US+_VccAux, US+_VccBRAM, US+_VccInt

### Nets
GND_FPGA_DECAP: C738.2 C739.2 C740.1 C741.1 C742.2 C743.1 C744.1 C745.1 C746.1 C747.2 C748.1 C749.1 C750.1 C751.2 C752.1 C753.2 C754.1 C755.1 C756.1 C757.2 C758.1 C759.1 C760.2 C761.1 C762.2 C763.1 C764.2 C765.1 ; port Ground  [project net B503_Ground]
US+_MGTAVTT: C741.2 C760.1 C761.2 ; port US+_MGTAVTT, port US+_Vcc_PS_PLL  [also labelled US+_Vcc_PS_PLL]  [project net RAM_Vcc1V2]
US+_PS_MGTRAVCC: C746.2 ; port US+_PS_MGTRAVCC  [project net 0V85@2A]
US+_Vcc_PS_Aux: C749.2 C750.2 C757.1 C758.2 ; port US+_VccAux, port US+_Vcc_PS_AUX  [also labelled US+_VccAux_io]  [project net 1V8@0.5A_ADC_filtered]
US+_Vcc_PS_Batt: C747.1 C748.2 ; port US+_Vcc_PS_Batt
US+_Vcc_PS_DDR_504: C753.1 C754.2 C755.2 ; port US+_Vcc_PS_DDR_504
US+_Vcc_PS_IntFp: C738.1 C739.1 C740.2 C744.2 C745.2 C751.1 C752.2 C762.1 C763.2 C764.1 C765.2 ; port US+_VccInt, port US+_VccBRAM, port US+_Vcc_PS_IntLp, port US+_Vcc_PS_IntFp, port US+_Vcc_PS_IntFpDDR  [also labelled US+_Vcc_PS_IntFpDDR, US+_Vcc_PS_IntLp, US+_VccBRAM, US+_VccInt, US+_VccInt_io]
US+_Vcc_PSIO: C742.1 C743.2 ; port US+_Vcc_PSIO  [also labelled US+_Vcc_PSIO_500, US+_Vcc_PSIO_501, US+_Vcc_PSIO_502, US+_Vcc_PSIO_503]  [project net ETH_VDDIO]
US+_Vcco_45: C756.2 C759.2 ; port US+_HPIO, port US+_HDIO  [also labelled US+_Vcco_46, US+_Vcco_64, US+_Vcco_65, US+_Vcco_66]  [project net US+_MGTVccAux]

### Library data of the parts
C738 C?#1 = 6TPE680MI: CAP TANT POLY 680UF 6.3V 2917; Manufacturer: Panasonic; Tolerance: 20%; ESR (Equivalent Series Resistance): 18mR; Ripple Current: 3.5A; Leakage Current: 428.4uA; Polarity: Polar; Dissipation Factor: 15%
C739 C742 C747 C751 C753 C757 C760 C762 C764 C?#2 = Capacitor: Manufacturer: Murata; Manufacturer Part Number: GRM32EE70G107ME19L; Material: Ceramic; Tolerance: 20%; Dielectric: X7U
C740 C741 C743 C745 C746 C748 C750 C752 C754 C755 C758 C761 C763 C765 C?#4 = Capacitor: Manufacturer: Murata; Manufacturer Part Number: GRM155R61A475MEAAD; Tolerance: 20%
C744 C749 C756 C759 C?#3 = Capacitor: Manufacturer: KEMET; Manufacturer Part Number: C1206C476M8PACTU; Dielectric Material: Ceramic; Tolerance: 20%; Dielectric: X5R

## Sheet RAM.SchDoc: RAM
size A3; Organization: PnP Systems Sp. z o.o.; Address1: Jasionka 954; Address2: 36-002  Jasionka, Poland; Address3: Phone: +48 17 773 69 10; Address4: e-mail: info@pnpsystems.com.pl
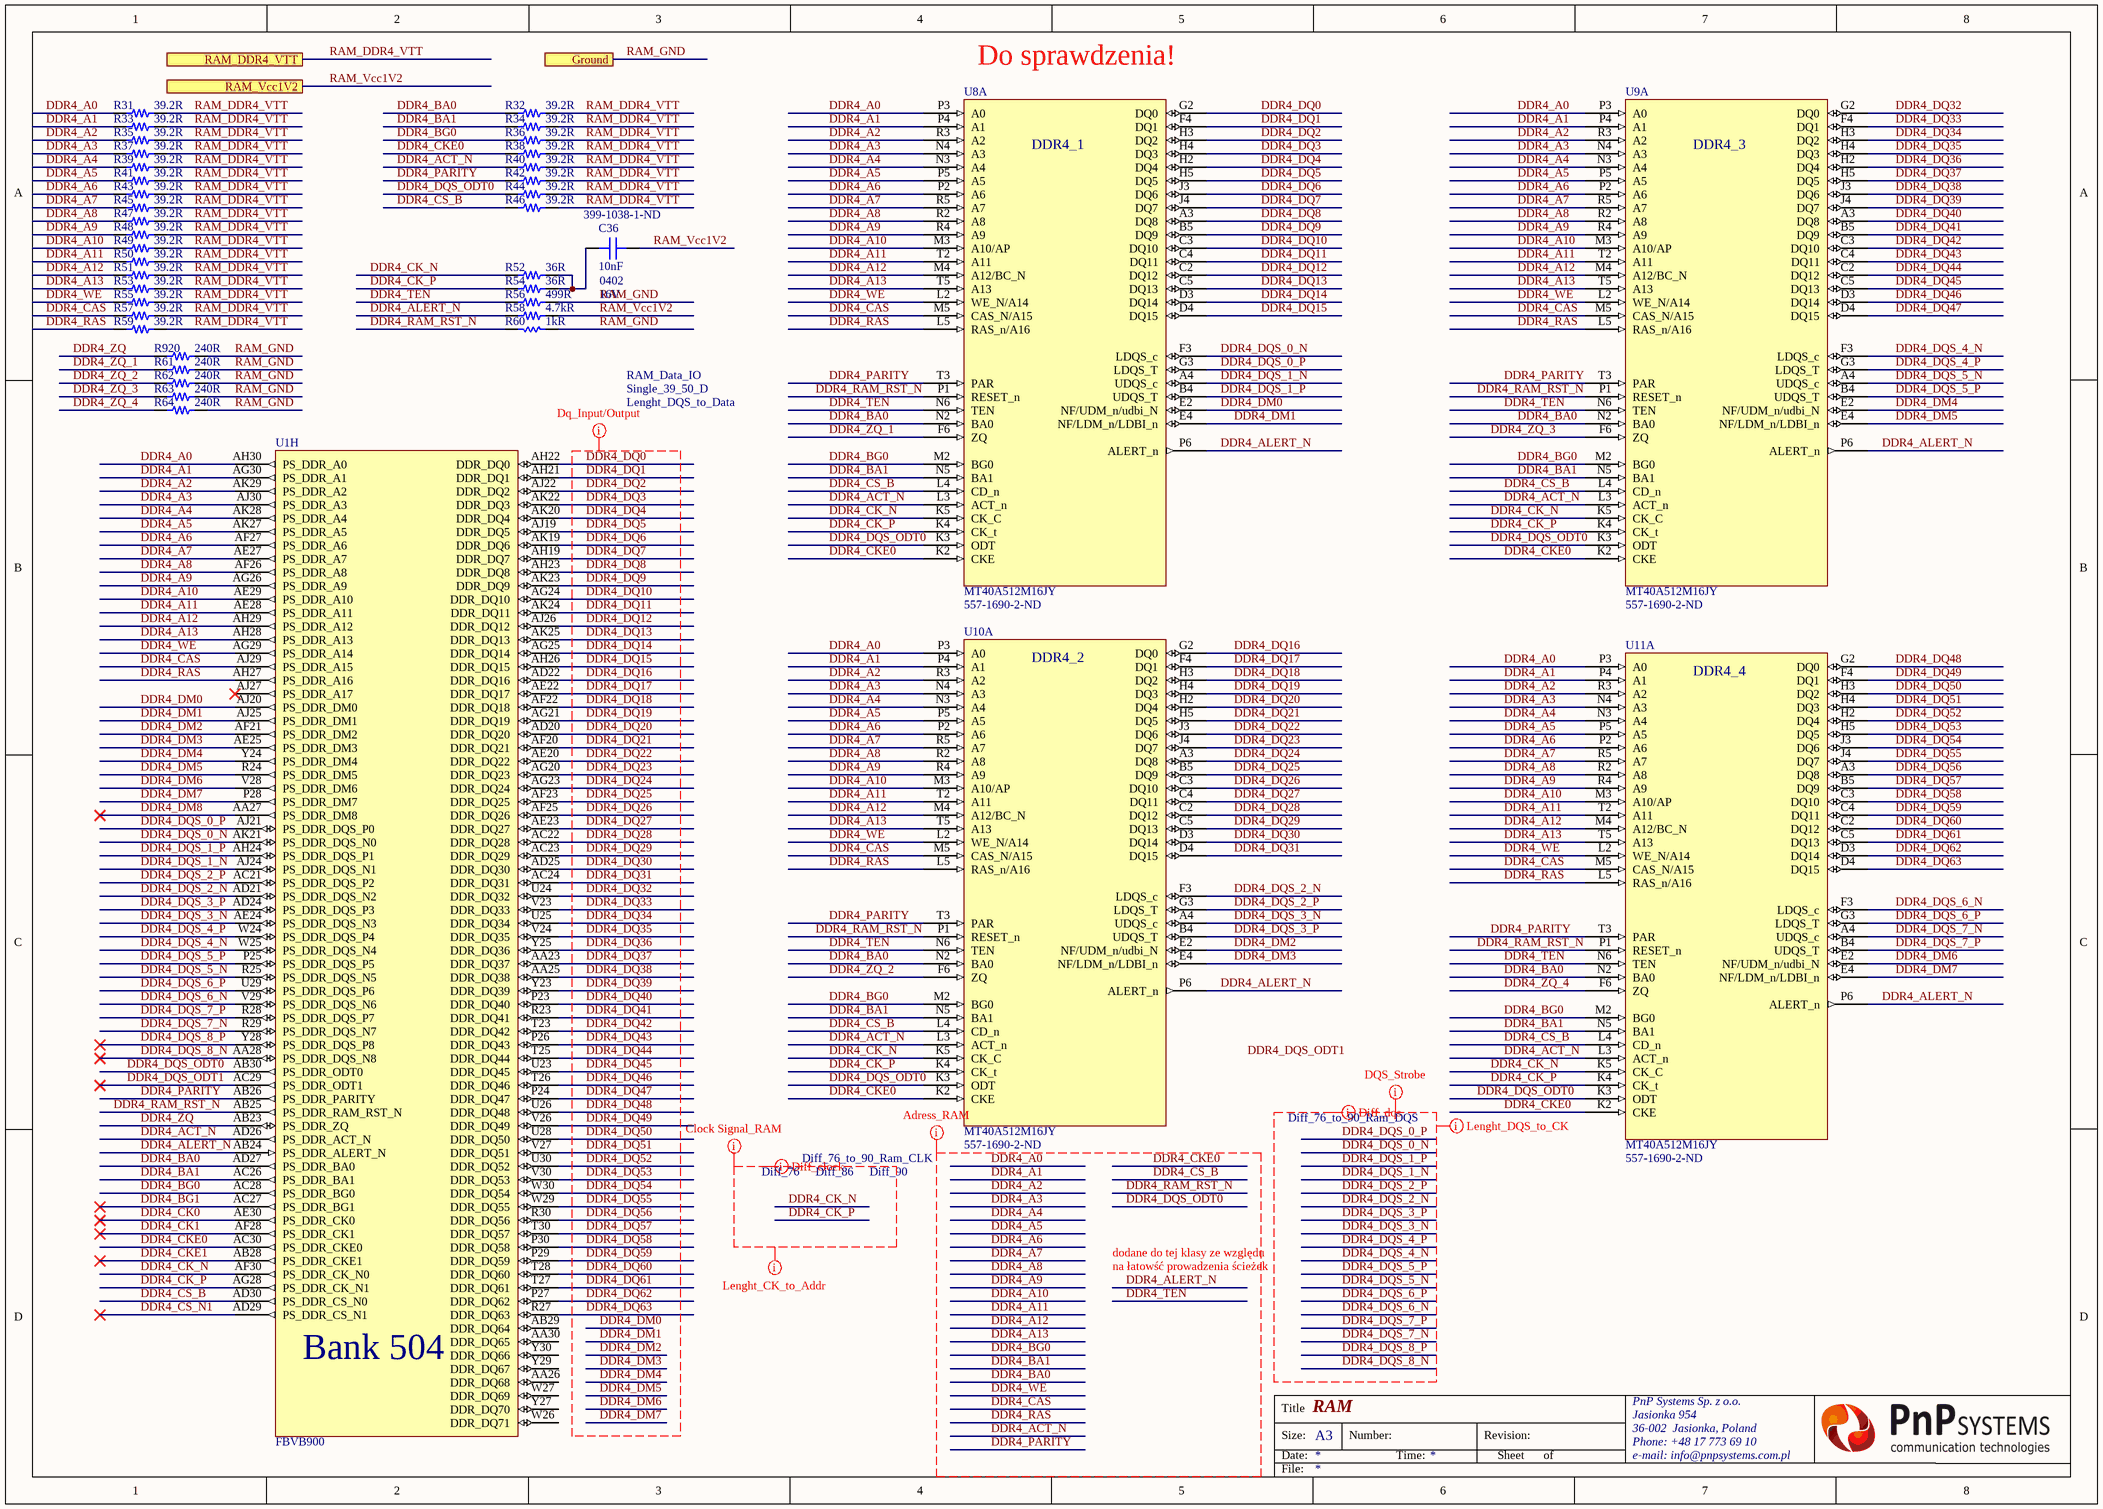
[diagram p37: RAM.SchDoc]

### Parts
C36  10nF  Supplier Part Number 1: 399-1038-1-ND  Case/Package: 0402  Voltage Rating (DC): 16V  [CAP 0402/1005 KK]
R31  39.2R  [RES 0402/1005 RF KK]
R32  39.2R  [RES 0402/1005 RF KK]
R33  39.2R  [RES 0402/1005 RF KK]
R34  39.2R  [RES 0402/1005 RF KK]
R35  39.2R  [RES 0402/1005 RF KK]
R36  39.2R  [RES 0402/1005 RF KK]
R37  39.2R  [RES 0402/1005 RF KK]
R38  39.2R  [RES 0402/1005 RF KK]
R39  39.2R  [RES 0402/1005 RF KK]
R40  39.2R  [RES 0402/1005 RF KK]
R41  39.2R  [RES 0402/1005 RF KK]
R42  39.2R  [RES 0402/1005 RF KK]
R43  39.2R  [RES 0402/1005 RF KK]
R44  39.2R  [RES 0402/1005 RF KK]
R45  39.2R  [RES 0402/1005 RF KK]
R46  39.2R  [RES 0402/1005 RF KK]
R47  39.2R  [RES 0402/1005 RF KK]
R48  39.2R  [RES 0402/1005 RF KK]
R49  39.2R  [RES 0402/1005 RF KK]
R50  39.2R  [RES 0402/1005 RF KK]
R51  39.2R  [RES 0402/1005 RF KK]
R52  36R  [RES 0402/1005 RF KK]
R53  39.2R  [RES 0402/1005 RF KK]
R54  36R  [RES 0402/1005 RF KK]
R55  39.2R  [RES 0402/1005 RF KK]
R56  499R  [RES 0402/1005 RF KK]
R57  39.2R  [RES 0402/1005 RF KK]
R58  4.7kR  [RES 0402/1005 RF KK]
R59  39.2R  [RES 0402/1005 RF KK]
R60  1kR  [RES 0402/1005 RF KK]
R61  240R  [RES 0402/1005 RF KK]
R62  240R  [RES 0402/1005 RF KK]
R63  240R  [RES 0402/1005 RF KK]
R64  240R  [RES 0402/1005 RF KK]
R920  240R  [RES 0402/1005 RF KK]
U1  FBVB900  [FBVB900 XX]  (part H of 23)
U8  MT40A512M16JY  Supplier Part Number 1: 557-1690-2-ND  [MT40A512M16JY]  (part A of 2)
U9  MT40A512M16JY  Supplier Part Number 1: 557-1690-2-ND  [MT40A512M16JY]  (part A of 2)
U10  MT40A512M16JY  Supplier Part Number 1: 557-1690-2-ND  [MT40A512M16JY]  (part A of 2)
U11  MT40A512M16JY  Supplier Part Number 1: 557-1690-2-ND  [MT40A512M16JY]  (part A of 2)

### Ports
Ground, RAM_DDR4_VTT, RAM_Vcc1V2

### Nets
RAM_GND: R56.2 R60.2 R61.2 R62.2 R63.2 R64.2 R920.2 ; port Ground  [project net B503_Ground]
DDR4_A0: R31.1 U1.AH30(PS_DDR_A0) U8.P3(A0) U9.P3(A0) U10.P3(A0) U11.P3(A0)
DDR4_A1: R33.1 U1.AG30(PS_DDR_A1) U8.P4(A1) U9.P4(A1) U10.P4(A1) U11.P4(A1)
DDR4_A2: R35.1 U1.AK29(PS_DDR_A2) U8.R3(A2) U9.R3(A2) U10.R3(A2) U11.R3(A2)
DDR4_A3: R37.1 U1.AJ30(PS_DDR_A3) U8.N4(A3) U9.N4(A3) U10.N4(A3) U11.N4(A3)
DDR4_A4: R39.1 U1.AK28(PS_DDR_A4) U8.N3(A4) U9.N3(A4) U10.N3(A4) U11.N3(A4)
DDR4_A5: R41.1 U1.AK27(PS_DDR_A5) U8.P5(A5) U9.P5(A5) U10.P5(A5) U11.P5(A5)
DDR4_A6: R43.1 U1.AF27(PS_DDR_A6) U8.P2(A6) U9.P2(A6) U10.P2(A6) U11.P2(A6)
DDR4_A7: R45.1 U1.AE27(PS_DDR_A7) U8.R5(A7) U9.R5(A7) U10.R5(A7) U11.R5(A7)
DDR4_A8: R47.1 U1.AF26(PS_DDR_A8) U8.R2(A8) U9.R2(A8) U10.R2(A8) U11.R2(A8)
DDR4_A9: R48.1 U1.AG26(PS_DDR_A9) U8.R4(A9) U9.R4(A9) U10.R4(A9) U11.R4(A9)
DDR4_A10: R49.1 U1.AE29(PS_DDR_A10) U8.M3(A10/AP) U9.M3(A10/AP) U10.M3(A10/AP) U11.M3(A10/AP)
DDR4_A11: R50.1 U1.AE28(PS_DDR_A11) U8.T2(A11) U9.T2(A11) U10.T2(A11) U11.T2(A11)
DDR4_A12: R51.1 U1.AH29(PS_DDR_A12) U8.M4(A12/BC_N) U9.M4(A12/BC_N) U10.M4(A12/BC_N) U11.M4(A12/BC_N)
DDR4_A13: R53.1 U1.AH28(PS_DDR_A13) U8.T5(A13) U9.T5(A13) U10.T5(A13) U11.T5(A13)
DDR4_ACT_N: R40.1 U1.AD26(PS_DDR_ACT_N) U8.L3(ACT_n) U9.L3(ACT_n) U10.L3(ACT_n) U11.L3(ACT_n)
DDR4_ALERT_N: R58.1 U1.AB24(PS_DDR_ALERT_N) U8.P6(ALERT_n) U9.P6(ALERT_n) U10.P6(ALERT_n) U11.P6(ALERT_n)
DDR4_BA0: R32.1 U1.AD27(PS_DDR_BA0) U8.N2(BA0) U9.N2(BA0) U10.N2(BA0) U11.N2(BA0)
DDR4_BA1: R34.1 U1.AC26(PS_DDR_BA1) U8.N5(BA1) U9.N5(BA1) U10.N5(BA1) U11.N5(BA1)
DDR4_BG0: R36.1 U1.AC28(PS_DDR_BG0) U8.M2(BG0) U9.M2(BG0) U10.M2(BG0) U11.M2(BG0)
DDR4_BG1: U1.AC27(PS_DDR_BG1)
DDR4_CAS: R57.1 U1.AJ29(PS_DDR_A15) U8.M5(CAS_N/A15) U9.M5(CAS_N/A15) U10.M5(CAS_N/A15) U11.M5(CAS_N/A15)
DDR4_CK0: U1.AE30(PS_DDR_CK0)
DDR4_CK1: U1.AF28(PS_DDR_CK1)
DDR4_CK_N: R52.1 U1.AF30(PS_DDR_CK_N0) U8.K5(CK_C) U9.K5(CK_C) U10.K5(CK_C) U11.K5(CK_C)
DDR4_CK_P: R54.1 U1.AG28(PS_DDR_CK_N1) U8.K4(CK_t) U9.K4(CK_t) U10.K4(CK_t) U11.K4(CK_t)
DDR4_CKE0: R38.1 U1.AC30(PS_DDR_CKE0) U8.K2(CKE) U9.K2(CKE) U10.K2(CKE) U11.K2(CKE)
DDR4_CKE1: U1.AB28(PS_DDR_CKE1)
DDR4_CS_B: R46.1 U1.AD30(PS_DDR_CS_N0) U8.L4(CD_n) U9.L4(CD_n) U10.L4(CD_n) U11.L4(CD_n)
DDR4_CS_N1: U1.AD29(PS_DDR_CS_N1)
DDR4_DM0: U1.AJ20(PS_DDR_DM0) U8.E2(NF/UDM_n/udbi_N)
DDR4_DM1: U1.AJ25(PS_DDR_DM1) U8.E4(NF/LDM_n/LDBI_n)
DDR4_DM2: U1.AF21(PS_DDR_DM2) U10.E2(NF/UDM_n/udbi_N)
DDR4_DM3: U1.AE25(PS_DDR_DM3) U10.E4(NF/LDM_n/LDBI_n)
DDR4_DM4: U1.Y24(PS_DDR_DM4) U9.E2(NF/UDM_n/udbi_N)
DDR4_DM5: U1.R24(PS_DDR_DM5) U9.E4(NF/LDM_n/LDBI_n)
DDR4_DM6: U1.V28(PS_DDR_DM6) U11.E2(NF/UDM_n/udbi_N)
DDR4_DM7: U1.P28(PS_DDR_DM7) U11.E4(NF/LDM_n/LDBI_n)
DDR4_DM8: U1.AA27(PS_DDR_DM8)
DDR4_DQ0: U1.AH22(DDR_DQ0) U8.G2(DQ0)
DDR4_DQ1: U1.AH21(DDR_DQ1) U8.F4(DQ1)
DDR4_DQ2: U1.AJ22(DDR_DQ2) U8.H3(DQ2)
DDR4_DQ3: U1.AK22(DDR_DQ3) U8.H4(DQ3)
DDR4_DQ4: U1.AK20(DDR_DQ4) U8.H2(DQ4)
DDR4_DQ5: U1.AJ19(DDR_DQ5) U8.H5(DQ5)
DDR4_DQ6: U1.AK19(DDR_DQ6) U8.J3(DQ6)
DDR4_DQ7: U1.AH19(DDR_DQ7) U8.J4(DQ7)
DDR4_DQ8: U1.AH23(DDR_DQ8) U8.A3(DQ8)
DDR4_DQ9: U1.AK23(DDR_DQ9) U8.B5(DQ9)
DDR4_DQ10: U1.AG24(DDR_DQ10) U8.C3(DQ10)
DDR4_DQ11: U1.AK24(DDR_DQ11) U8.C4(DQ11)
DDR4_DQ12: U1.AJ26(DDR_DQ12) U8.C2(DQ12)
DDR4_DQ13: U1.AK25(DDR_DQ13) U8.C5(DQ13)
DDR4_DQ14: U1.AG25(DDR_DQ14) U8.D3(DQ14)
DDR4_DQ15: U1.AH26(DDR_DQ15) U8.D4(DQ15)
DDR4_DQ16: U1.AD22(DDR_DQ16) U10.G2(DQ0)
DDR4_DQ17: U1.AE22(DDR_DQ17) U10.F4(DQ1)
DDR4_DQ18: U1.AF22(DDR_DQ18) U10.H3(DQ2)
DDR4_DQ19: U1.AG21(DDR_DQ19) U10.H4(DQ3)
DDR4_DQ20: U1.AD20(DDR_DQ20) U10.H2(DQ4)
DDR4_DQ21: U1.AF20(DDR_DQ21) U10.H5(DQ5)
DDR4_DQ22: U1.AE20(DDR_DQ22) U10.J3(DQ6)
DDR4_DQ23: U1.AG20(DDR_DQ23) U10.J4(DQ7)
DDR4_DQ24: U1.AG23(DDR_DQ24) U10.A3(DQ8)
DDR4_DQ25: U1.AF23(DDR_DQ25) U10.B5(DQ9)
DDR4_DQ26: U1.AF25(DDR_DQ26) U10.C3(DQ10)
DDR4_DQ27: U1.AE23(DDR_DQ27) U10.C4(DQ11)
DDR4_DQ28: U1.AC22(DDR_DQ28) U10.C2(DQ12)
DDR4_DQ29: U1.AC23(DDR_DQ29) U10.C5(DQ13)
DDR4_DQ30: U1.AD25(DDR_DQ30) U10.D3(DQ14)
DDR4_DQ31: U1.AC24(DDR_DQ31) U10.D4(DQ15)
DDR4_DQ32: U1.U24(DDR_DQ32) U9.G2(DQ0)
DDR4_DQ33: U1.V23(DDR_DQ33) U9.F4(DQ1)
DDR4_DQ34: U1.U25(DDR_DQ34) U9.H3(DQ2)
DDR4_DQ35: U1.V24(DDR_DQ35) U9.H4(DQ3)
DDR4_DQ36: U1.Y25(DDR_DQ36) U9.H2(DQ4)
DDR4_DQ37: U1.AA23(DDR_DQ37) U9.H5(DQ5)
DDR4_DQ38: U1.AA25(DDR_DQ38) U9.J3(DQ6)
DDR4_DQ39: U1.Y23(DDR_DQ39) U9.J4(DQ7)
DDR4_DQ40: U1.P23(DDR_DQ40) U9.A3(DQ8)
DDR4_DQ41: U1.R23(DDR_DQ41) U9.B5(DQ9)
DDR4_DQ42: U1.T23(DDR_DQ42) U9.C3(DQ10)
DDR4_DQ43: U1.P26(DDR_DQ43) U9.C4(DQ11)
DDR4_DQ44: U1.T25(DDR_DQ44) U9.C2(DQ12)
DDR4_DQ45: U1.U23(DDR_DQ45) U9.C5(DQ13)
DDR4_DQ46: U1.T26(DDR_DQ46) U9.D3(DQ14)
DDR4_DQ47: U1.P24(DDR_DQ47) U9.D4(DQ15)
DDR4_DQ48: U1.U26(DDR_DQ48) U11.G2(DQ0)
DDR4_DQ49: U1.V26(DDR_DQ49) U11.F4(DQ1)
DDR4_DQ50: U1.U28(DDR_DQ50) U11.H3(DQ2)
DDR4_DQ51: U1.V27(DDR_DQ51) U11.H4(DQ3)
DDR4_DQ52: U1.U30(DDR_DQ52) U11.H2(DQ4)
DDR4_DQ53: U1.V30(DDR_DQ53) U11.H5(DQ5)
DDR4_DQ54: U1.W30(DDR_DQ54) U11.J3(DQ6)
DDR4_DQ55: U1.W29(DDR_DQ55) U11.J4(DQ7)
DDR4_DQ56: U1.R30(DDR_DQ56) U11.A3(DQ8)
DDR4_DQ57: U1.T30(DDR_DQ57) U11.B5(DQ9)
DDR4_DQ58: U1.P30(DDR_DQ58) U11.C3(DQ10)
DDR4_DQ59: U1.P29(DDR_DQ59) U11.C4(DQ11)
DDR4_DQ60: U1.T28(DDR_DQ60) U11.C2(DQ12)
DDR4_DQ61: U1.T27(DDR_DQ61) U11.C5(DQ13)
DDR4_DQ62: U1.P27(DDR_DQ62) U11.D3(DQ14)
DDR4_DQ63: U1.R27(DDR_DQ63) U11.D4(DQ15)
DDR4_DQS_0_N: U1.AK21(PS_DDR_DQS_N0) U8.F3(LDQS_c)
DDR4_DQS_0_P: U1.AJ21(PS_DDR_DQS_P0) U8.G3(LDQS_T)
DDR4_DQS_1_N: U1.AJ24(PS_DDR_DQS_N1) U8.A4(UDQS_c)
DDR4_DQS_1_P: U1.AH24(PS_DDR_DQS_P1) U8.B4(UDQS_T)
DDR4_DQS_2_N: U1.AD21(PS_DDR_DQS_N2) U10.F3(LDQS_c)
DDR4_DQS_2_P: U1.AC21(PS_DDR_DQS_P2) U10.G3(LDQS_T)
DDR4_DQS_3_N: U1.AE24(PS_DDR_DQS_N3) U10.A4(UDQS_c)
DDR4_DQS_3_P: U1.AD24(PS_DDR_DQS_P3) U10.B4(UDQS_T)
DDR4_DQS_4_N: U1.W25(PS_DDR_DQS_N4) U9.F3(LDQS_c)
DDR4_DQS_4_P: U1.W24(PS_DDR_DQS_P4) U9.G3(LDQS_T)
DDR4_DQS_5_N: U1.R25(PS_DDR_DQS_N5) U9.A4(UDQS_c)
DDR4_DQS_5_P: U1.P25(PS_DDR_DQS_P5) U9.B4(UDQS_T)
DDR4_DQS_6_N: U1.V29(PS_DDR_DQS_N6) U11.F3(LDQS_c)
DDR4_DQS_6_P: U1.U29(PS_DDR_DQS_P6) U11.G3(LDQS_T)
DDR4_DQS_7_N: U1.R29(PS_DDR_DQS_N7) U11.A4(UDQS_c)
DDR4_DQS_7_P: U1.R28(PS_DDR_DQS_P7) U11.B4(UDQS_T)
DDR4_DQS_8_N: U1.AA28(PS_DDR_DQS_N8)
DDR4_DQS_8_P: U1.Y28(PS_DDR_DQS_P8)
DDR4_DQS_ODT0: R44.1 U1.AB30(PS_DDR_ODT0) U8.K3(ODT) U9.K3(ODT) U10.K3(ODT) U11.K3(ODT)
DDR4_DQS_ODT1: U1.AC29(PS_DDR_ODT1)
DDR4_PARITY: R42.1 U1.AB26(PS_DDR_PARITY) U8.T3(PAR) U9.T3(PAR) U10.T3(PAR) U11.T3(PAR)
DDR4_RAM_RST_N: R60.1 U1.AB25(PS_DDR_RAM_RST_N) U8.P1(RESET_n) U9.P1(RESET_n) U10.P1(RESET_n) U11.P1(RESET_n)
DDR4_RAS: R59.1 U1.AH27(PS_DDR_A16) U8.L5(RAS_n/A16) U9.L5(RAS_n/A16) U10.L5(RAS_n/A16) U11.L5(RAS_n/A16)
DDR4_TEN: R56.1 U8.N6(TEN) U9.N6(TEN) U10.N6(TEN) U11.N6(TEN)
DDR4_WE: R55.1 U1.AG29(PS_DDR_A14) U8.L2(WE_N/A14) U9.L2(WE_N/A14) U10.L2(WE_N/A14) U11.L2(WE_N/A14)
DDR4_ZQ: R920.1 U1.AB23(PS_DDR_ZQ)
DDR4_ZQ_1: R61.1 U8.F6(ZQ)
DDR4_ZQ_2: R62.1 U10.F6(ZQ)
DDR4_ZQ_3: R63.1 U9.F6(ZQ)
DDR4_ZQ_4: R64.1 U11.F6(ZQ)
RAM_DDR4_VTT: R31.2 R32.2 R33.2 R34.2 R35.2 R36.2 R37.2 R38.2 R39.2 R40.2 R41.2 R42.2 R43.2 R44.2 R45.2 R46.2 R47.2 R48.2 R49.2 R50.2 R51.2 R53.2 R55.2 R57.2 R59.2 ; port RAM_DDR4_VTT
RAM_Vcc1V2: C36.2 R58.2 ; port RAM_Vcc1V2
NetC36_1: C36.1 R52.2 R54.2

Not connected (* = marked no-connect by the designer): U1 AA26(DDR_DQ68) AA30(DDR_DQ65) AB29(DDR_DQ64) AJ27(PS_DDR_A17)* W26(DDR_DQ71) W27(DDR_DQ69) Y27(DDR_DQ70) Y29(DDR_DQ67) Y30(DDR_DQ66)

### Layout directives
net class RAM_Clock_Signal: DDR4_CK_N, DDR4_CK_P
differential pair; differential pair class Diff_76_to_90_Ram_CLK; differential pair class Diff_76; differential pair class Diff_86; differential pair class Diff_90: DDR4_CK_N, DDR4_CK_P
net class Single_36_39_50_Adr; net class RAM_Adress: DDR4_A0, DDR4_A1, DDR4_A2, DDR4_A3, DDR4_A4, DDR4_A5, DDR4_A6, DDR4_A7, DDR4_A8, DDR4_A9, DDR4_A10, DDR4_A11, DDR4_A12, DDR4_A13, DDR4_ACT_N, DDR4_ALERT_N, DDR4_BA0, DDR4_BA1, DDR4_BG0, DDR4_CAS, DDR4_CKE0, DDR4_CS_B, DDR4_DQS_ODT0, DDR4_PARITY, DDR4_RAM_RST_N, DDR4_RAS, DDR4_TEN, DDR4_WE
net class Diff_76_86_90; net class RAM_DQS_Strobe: DDR4_DQS_0_N, DDR4_DQS_0_P, DDR4_DQS_1_N, DDR4_DQS_1_P, DDR4_DQS_2_N, DDR4_DQS_2_P, DDR4_DQS_3_N, DDR4_DQS_3_P, DDR4_DQS_4_N, DDR4_DQS_4_P, DDR4_DQS_5_N, DDR4_DQS_5_P, DDR4_DQS_6_N, DDR4_DQS_6_P, DDR4_DQS_7_N, DDR4_DQS_7_P, DDR4_DQS_8_N, DDR4_DQS_8_P
net class Single_39_50_D; net class RAM_Data_IO; net class Lenght_DQS_to_Data: DDR4_DM0, DDR4_DM1, DDR4_DM2, DDR4_DM3, DDR4_DM4, DDR4_DM5, DDR4_DM6, DDR4_DM7, DDR4_DQ0, DDR4_DQ1, DDR4_DQ2, DDR4_DQ3, DDR4_DQ4, DDR4_DQ5, DDR4_DQ6, DDR4_DQ7, DDR4_DQ8, DDR4_DQ9, DDR4_DQ10, DDR4_DQ11, DDR4_DQ12, DDR4_DQ13, DDR4_DQ14, DDR4_DQ15, DDR4_DQ16, DDR4_DQ17, DDR4_DQ18, DDR4_DQ19, DDR4_DQ20, DDR4_DQ21, DDR4_DQ22, DDR4_DQ23, DDR4_DQ24, DDR4_DQ25, DDR4_DQ26, DDR4_DQ27, DDR4_DQ28, DDR4_DQ29, DDR4_DQ30, DDR4_DQ31, DDR4_DQ32, DDR4_DQ33, DDR4_DQ34, DDR4_DQ35, DDR4_DQ36, DDR4_DQ37, DDR4_DQ38, DDR4_DQ39, DDR4_DQ40, DDR4_DQ41, DDR4_DQ42, DDR4_DQ43, DDR4_DQ44, DDR4_DQ45, DDR4_DQ46, DDR4_DQ47, DDR4_DQ48, DDR4_DQ49, DDR4_DQ50, DDR4_DQ51, DDR4_DQ52, DDR4_DQ53, DDR4_DQ54, DDR4_DQ55, DDR4_DQ56, DDR4_DQ57, DDR4_DQ58, DDR4_DQ59, DDR4_DQ60, DDR4_DQ61, DDR4_DQ62, DDR4_DQ63
differential pair; differential pair class Diff_76_to_90_Ram_DQS: DDR4_DQS_0_N, DDR4_DQS_0_P, DDR4_DQS_1_N, DDR4_DQS_1_P, DDR4_DQS_2_N, DDR4_DQS_2_P, DDR4_DQS_3_N, DDR4_DQS_3_P, DDR4_DQS_4_N, DDR4_DQS_4_P, DDR4_DQS_5_N, DDR4_DQS_5_P, DDR4_DQS_6_N, DDR4_DQS_6_P, DDR4_DQS_7_N, DDR4_DQS_7_P, DDR4_DQS_8_N, DDR4_DQS_8_P
net class Lenght_CK_to_Addr: DDR4_CK_N, DDR4_CK_P
net class Lenght_DQS_to_CK: DDR4_DQS_0_N, DDR4_DQS_0_P, DDR4_DQS_1_N, DDR4_DQS_1_P, DDR4_DQS_2_N, DDR4_DQS_2_P, DDR4_DQS_3_N, DDR4_DQS_3_P, DDR4_DQS_4_N, DDR4_DQS_4_P, DDR4_DQS_5_N, DDR4_DQS_5_P, DDR4_DQS_6_N, DDR4_DQS_6_P, DDR4_DQS_7_N, DDR4_DQS_7_P, DDR4_DQS_8_N, DDR4_DQS_8_P

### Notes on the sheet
- (near U8) Do sprawdzenia!
- (near U8) DDR4_1
- (near U9) DDR4_3
- (near U10) DDR4_2
- (near U11) DDR4_4
- dodane do tej klasy ze względu
- na łatowść prowadzenia ścieżek
- Labels drawn without touching a wire or pin: DDR4_DQS_ODT1

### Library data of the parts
C36 = Capacitor: Manufacturer: KEMET; Manufacturer Part Number: C0402C103K4RACTU; Dielectric Material: Ceramic; Tolerance: 10%; Dielectric: X7R; Dissipation Factor: 3.5%
R31-R51 R53 R55 R57 R59 = Resistor: Manufacturer: Panasonic; Manufacturer Part Number: ERJ-2RKF39R2X; Tolerance: 1%; Temperature Coefficient: 100ppm/°C; Power Rating: 100mW; Voltage Rating: 50V
R52 R54 = Resistor: Manufacturer: Panasonic; Manufacturer Part Number: ERJ-2RKF36R0X; Tolerance: 1%; Temperature Coefficient: 100ppm/°C; Power Rating: 100mW; Voltage Rating: 50V
R56 = Resistor: Resistor;  Thick Film;  Res 499 Ohms;  Pwr-Rtg 0.1 W;  Tol 1%;  SMT;  0402;  Tape & Reel; Manufacturer: Panasonic; Manufacturer Part Number: ERJ-2RKF4990X; Power Rating: 100mW; Voltage Rating: 50V; Temperature Coefficient: 100ppm/°C
R58 = Resistor: as R276 on sheet XilinxPower
R60 = Resistor: PANASONIC - ERJ-2RKF1001X - SMD Chip Resistor, 0402 [1005 Metric], 1 kohm, ERJ2R Series, 50 V, Thick Film, 100 mW; Temperature Coefficient: 100ppm/°C; Tolerance: 1%; Voltage Rating (DC): 50V; Power Rating: 100mW
R61-R64 R920 = Resistor: Manufacturer: Vishay; Manufacturer Part Number: CRCW0402240RFKED; Tolerance: 1%; Power Rating: 63mW; Temperature Coefficient: 100ppm/°C; Voltage Rating: 50V
U1 = FBVB900: as U1 on sheet XilinxPower
U8-U11 = MT40A512M16JY: as U8 on sheet RAM_Power

## Sheet Ground.SchDoc: Minus komponentow
size A3; Organization: Altium Limited; Address1: L3, 12a Rodborough Rd; Address2: Frenchs Forest; Address3: NSW; Address4: Australia 2086
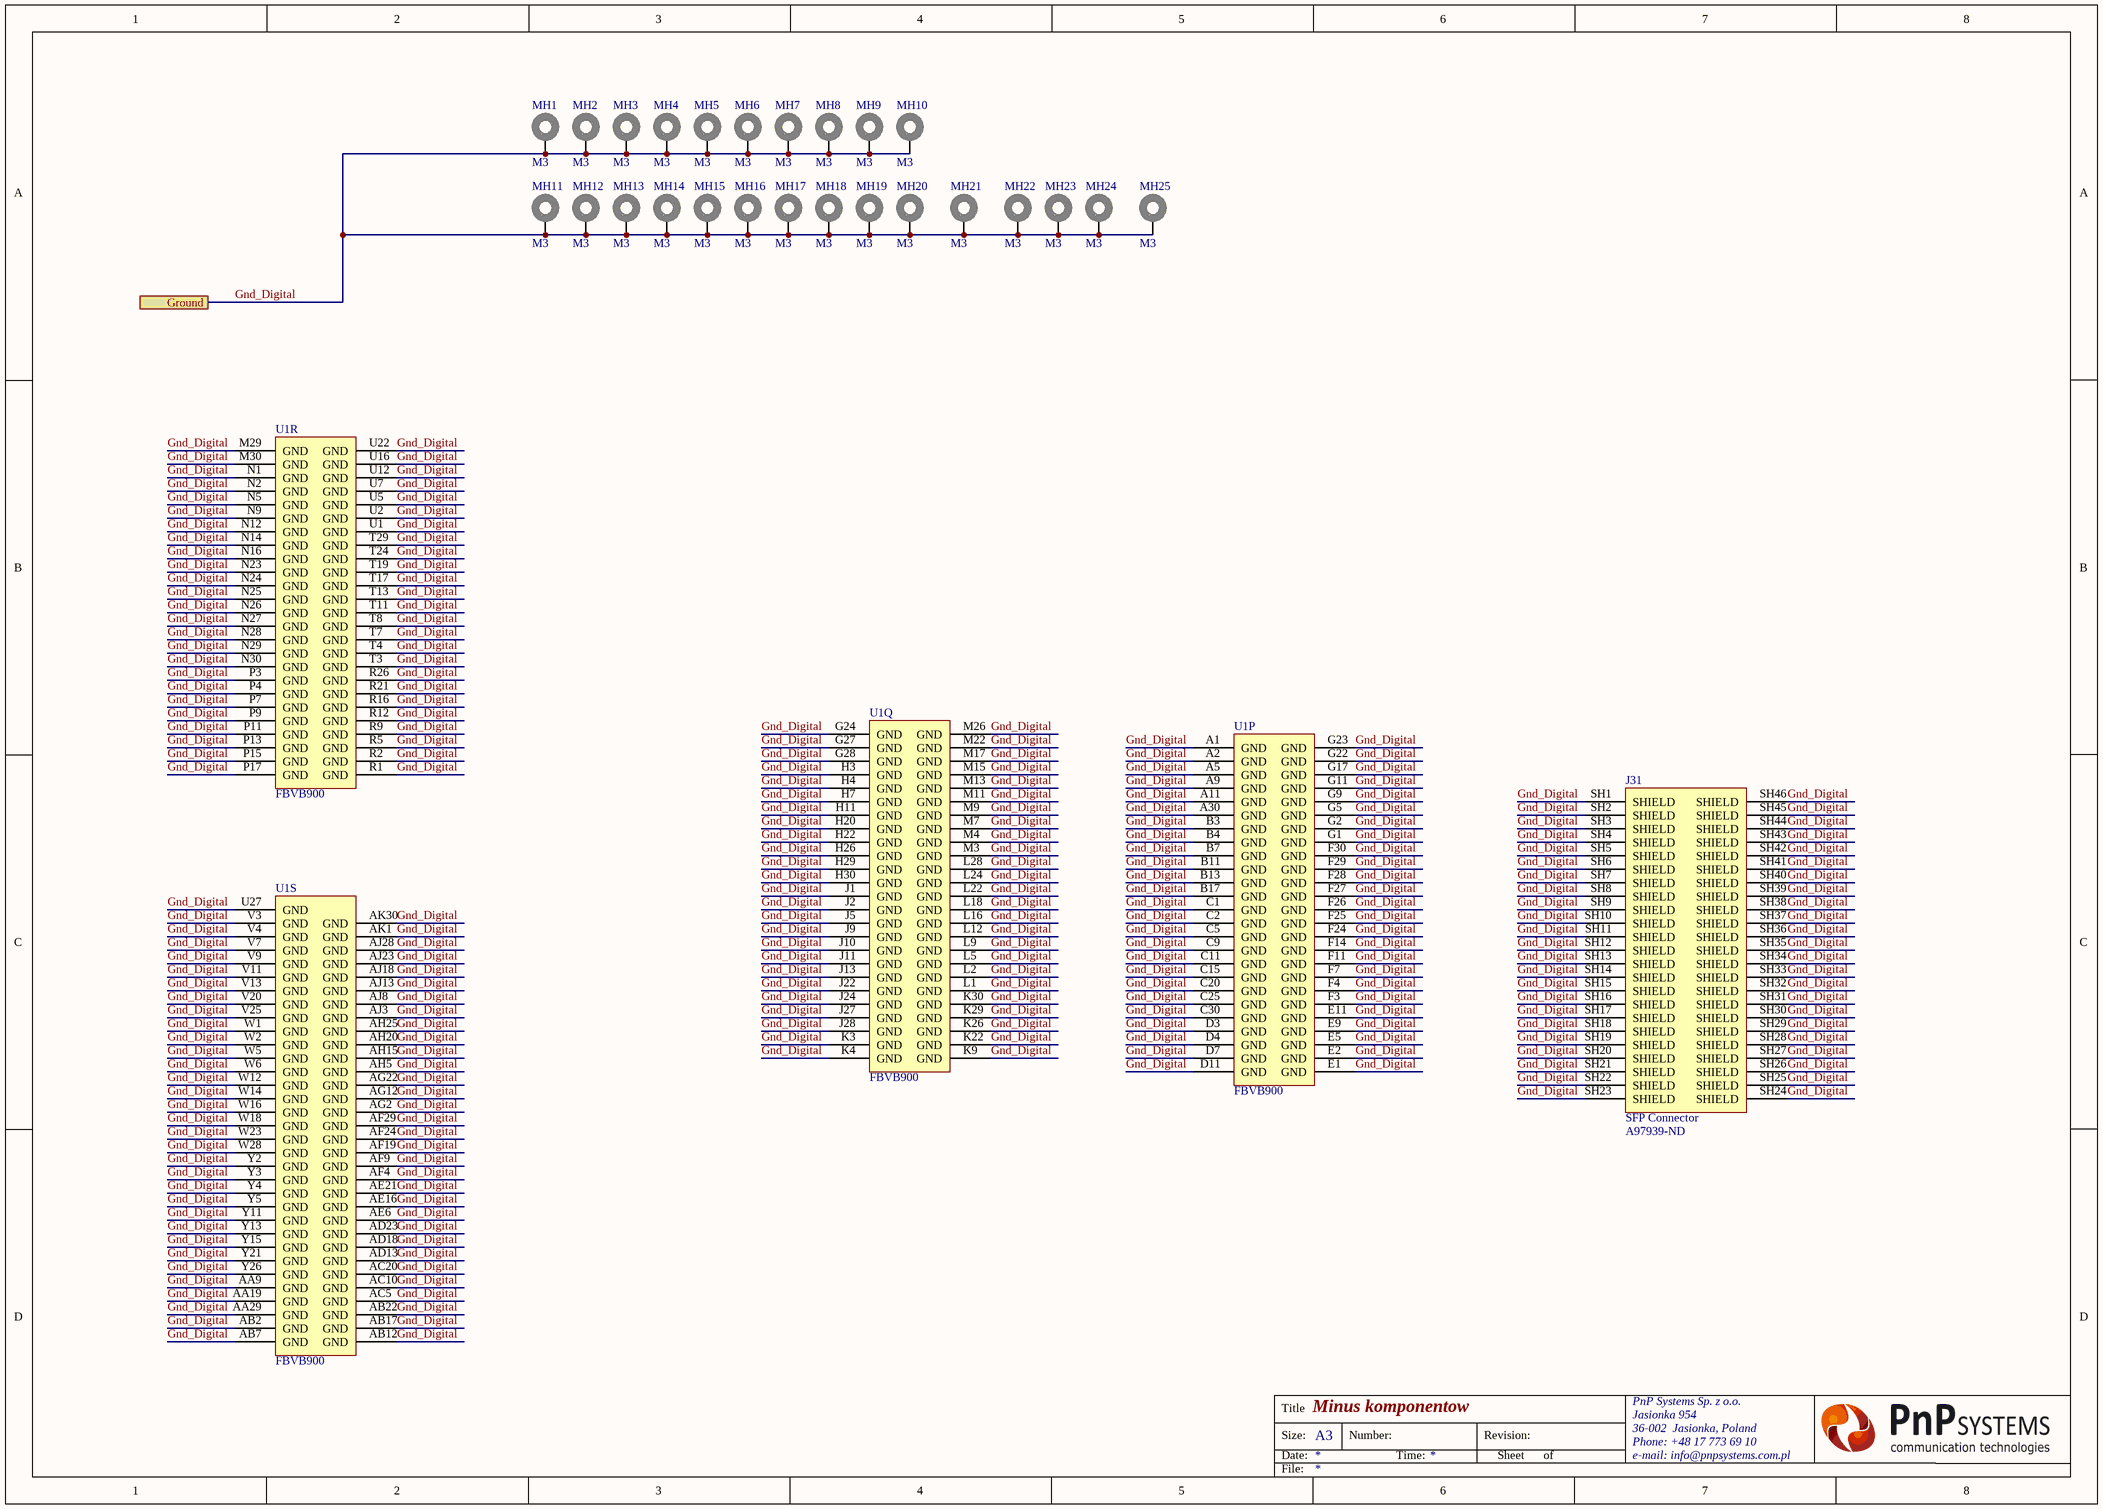
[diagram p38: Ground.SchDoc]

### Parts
J31  SFP Connector  Supplier Part Number 1: A97939-ND  [2007132]
MH1  Parameter 1: M3  [MH_5_3.2_SUB_VIA]  (hidden comment: MH_5_3.2)  (no BOM)
MH2  Parameter 1: M3  [MH_5_3.2_SUB_VIA]  (hidden comment: MH_5_3.2)  (no BOM)
MH3  Parameter 1: M3  [MH_5_3.2_SUB_VIA]  (hidden comment: MH_5_3.2)  (no BOM)
MH4  Parameter 1: M3  [MH_5_3.2_SUB_VIA]  (hidden comment: MH_5_3.2)  (no BOM)
MH5  Parameter 1: M3  [MH_5_3.2_SUB_VIA]  (hidden comment: MH_5_3.2)  (no BOM)
MH6  Parameter 1: M3  [MH_5_3.2_SUB_VIA]  (hidden comment: MH_5_3.2)  (no BOM)
MH7  Parameter 1: M3  [MH_5_3.2_SUB_VIA]  (hidden comment: MH_5_3.2)  (no BOM)
MH8  Parameter 1: M3  [MH_5_3.2_SUB_VIA]  (hidden comment: MH_5_3.2)  (no BOM)
MH9  Parameter 1: M3  [MH_5_3.2_SUB_VIA]  (hidden comment: MH_5_3.2)  (no BOM)
MH10  Parameter 1: M3  [MH_5_3.2_SUB_VIA]  (hidden comment: MH_5_3.2)  (no BOM)
MH11  Parameter 1: M3  [MH_5_3.2_SUB_VIA]  (hidden comment: MH_5_3.2)  (no BOM)
MH12  Parameter 1: M3  [MH_5_3.2_SUB_VIA]  (hidden comment: MH_5_3.2)  (no BOM)
MH13  Parameter 1: M3  [MH_5_3.2_SUB_VIA]  (hidden comment: MH_5_3.2)  (no BOM)
MH14  Parameter 1: M3  [MH_5_3.2_SUB_VIA]  (hidden comment: MH_5_3.2)  (no BOM)
MH15  Parameter 1: M3  [MH_5_3.2_SUB_VIA]  (hidden comment: MH_5_3.2)  (no BOM)
MH16  Parameter 1: M3  [MH_5_3.2_SUB_VIA]  (hidden comment: MH_5_3.2)  (no BOM)
MH17  Parameter 1: M3  [MH_5_3.2_SUB_VIA]  (hidden comment: MH_5_3.2)  (no BOM)
MH18  Parameter 1: M3  [MH_5_3.2_SUB_VIA]  (hidden comment: MH_5_3.2)  (no BOM)
MH19  Parameter 1: M3  [MH_5_3.2_SUB_VIA]  (hidden comment: MH_5_3.2)  (no BOM)
MH20  Parameter 1: M3  [MH_5_3.2_SUB_VIA]  (hidden comment: MH_5_3.2)  (no BOM)
MH21  Parameter 1: M3  [MH_5_3.2_SUB_VIA]  (hidden comment: MH_5_3.2)  (no BOM)
MH22  Parameter 1: M3  [MH_5_3.2_SUB_VIA]  (hidden comment: MH_5_3.2)  (no BOM)
MH23  Parameter 1: M3  [MH_5_3.2_SUB_VIA]  (hidden comment: MH_5_3.2)  (no BOM)
MH24  Parameter 1: M3  [MH_5_3.2_SUB_VIA]  (hidden comment: MH_5_3.2)  (no BOM)
MH25  Parameter 1: M3  [MH_5_3.2_SUB_VIA]  (hidden comment: MH_5_3.2)  (no BOM)
U1  FBVB900  [FBVB900 XX]  (parts P,Q,R,S of 23)

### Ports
Ground

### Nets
Gnd_Digital: J31.SH1(SHIELD) J31.SH2(SHIELD) J31.SH3(SHIELD) J31.SH4(SHIELD) J31.SH5(SHIELD) J31.SH6(SHIELD) J31.SH7(SHIELD) J31.SH8(SHIELD) J31.SH9(SHIELD) J31.SH10(SHIELD) J31.SH11(SHIELD) J31.SH12(SHIELD) J31.SH13(SHIELD) J31.SH14(SHIELD) J31.SH15(SHIELD) J31.SH16(SHIELD) J31.SH17(SHIELD) J31.SH18(SHIELD) J31.SH19(SHIELD) J31.SH20(SHIELD) J31.SH21(SHIELD) J31.SH22(SHIELD) J31.SH23(SHIELD) J31.SH24(SHIELD) J31.SH25(SHIELD) J31.SH26(SHIELD) J31.SH27(SHIELD) J31.SH28(SHIELD) J31.SH29(SHIELD) J31.SH30(SHIELD) J31.SH31(SHIELD) J31.SH32(SHIELD) J31.SH33(SHIELD) J31.SH34(SHIELD) J31.SH35(SHIELD) J31.SH36(SHIELD) J31.SH37(SHIELD) J31.SH38(SHIELD) J31.SH39(SHIELD) J31.SH40(SHIELD) J31.SH41(SHIELD) J31.SH42(SHIELD) J31.SH43(SHIELD) J31.SH44(SHIELD) J31.SH45(SHIELD) J31.SH46(SHIELD) MH1.1 MH2.1 MH3.1 MH4.1 MH5.1 MH6.1 MH7.1 MH8.1 MH9.1 MH10.1 MH11.1 MH12.1 MH13.1 MH14.1 MH15.1 MH16.1 MH17.1 MH18.1 MH19.1 MH20.1 MH21.1 MH22.1 MH23.1 MH24.1 MH25.1 U1.A1(GND) U1.A2(GND) U1.A5(GND) U1.A9(GND) U1.A11(GND) U1.A30(GND) U1.AA9(GND) U1.AA19(GND) U1.AA29(GND) U1.AB2(GND) U1.AB7(GND) U1.AB12(GND) U1.AB17(GND) U1.AB22(GND) U1.AC5(GND) U1.AC10(GND) U1.AC20(GND) U1.AD13(GND) U1.AD18(GND) U1.AD23(GND) U1.AE6(GND) U1.AE16(GND) U1.AE21(GND) U1.AF4(GND) U1.AF9(GND) U1.AF19(GND) U1.AF24(GND) U1.AF29(GND) U1.AG2(GND) U1.AG12(GND) U1.AG22(GND) U1.AH5(GND) U1.AH15(GND) U1.AH20(GND) U1.AH25(GND) U1.AJ3(GND) U1.AJ8(GND) U1.AJ13(GND) U1.AJ18(GND) U1.AJ23(GND) U1.AJ28(GND) U1.AK1(GND) U1.AK30(GND) U1.B3(GND) U1.B4(GND) U1.B7(GND) U1.B11(GND) U1.B13(GND) U1.B17(GND) U1.C1(GND) U1.C2(GND) U1.C5(GND) U1.C9(GND) U1.C11(GND) U1.C15(GND) U1.C20(GND) U1.C25(GND) U1.C30(GND) U1.D3(GND) U1.D4(GND) U1.D7(GND) U1.D11(GND) U1.E1(GND) U1.E2(GND) U1.E5(GND) U1.E9(GND) U1.E11(GND) U1.F3(GND) U1.F4(GND) U1.F7(GND) U1.F11(GND) U1.F14(GND) U1.F24(GND) U1.F25(GND) U1.F26(GND) U1.F27(GND) U1.F28(GND) U1.F29(GND) U1.F30(GND) U1.G1(GND) U1.G2(GND) U1.G5(GND) U1.G9(GND) U1.G11(GND) U1.G17(GND) U1.G22(GND) U1.G23(GND) U1.G24(GND) U1.G27(GND) U1.G28(GND) U1.H3(GND) U1.H4(GND) U1.H7(GND) U1.H11(GND) U1.H20(GND) U1.H22(GND) U1.H26(GND) U1.H29(GND) U1.H30(GND) U1.J1(GND) U1.J2(GND) U1.J5(GND) U1.J9(GND) U1.J10(GND) U1.J11(GND) U1.J13(GND) U1.J22(GND) U1.J24(GND) U1.J27(GND) U1.J28(GND) U1.K3(GND) U1.K4(GND) U1.K9(GND) U1.K22(GND) U1.K26(GND) U1.K29(GND) U1.K30(GND) U1.L1(GND) U1.L2(GND) U1.L5(GND) U1.L9(GND) U1.L12(GND) U1.L16(GND) U1.L18(GND) U1.L22(GND) U1.L24(GND) U1.L28(GND) U1.M3(GND) U1.M4(GND) U1.M7(GND) U1.M9(GND) U1.M11(GND) U1.M13(GND) U1.M15(GND) U1.M17(GND) U1.M22(GND) U1.M26(GND) U1.M29(GND) U1.M30(GND) U1.N1(GND) U1.N2(GND) U1.N5(GND) U1.N9(GND) U1.N12(GND) U1.N14(GND) U1.N16(GND) U1.N23(GND) U1.N24(GND) U1.N25(GND) U1.N26(GND) U1.N27(GND) U1.N28(GND) U1.N29(GND) U1.N30(GND) U1.P3(GND) U1.P4(GND) U1.P7(GND) U1.P9(GND) U1.P11(GND) U1.P13(GND) U1.P15(GND) U1.P17(GND) U1.R1(GND) U1.R2(GND) U1.R5(GND) U1.R9(GND) U1.R12(GND) U1.R16(GND) U1.R21(GND) U1.R26(GND) U1.T3(GND) U1.T4(GND) U1.T7(GND) U1.T8(GND) U1.T11(GND) U1.T13(GND) U1.T17(GND) U1.T19(GND) U1.T24(GND) U1.T29(GND) U1.U1(GND) U1.U2(GND) U1.U5(GND) U1.U7(GND) U1.U12(GND) U1.U16(GND) U1.U22(GND) U1.U27(GND) U1.V3(GND) U1.V4(GND) U1.V7(GND) U1.V9(GND) U1.V11(GND) U1.V13(GND) U1.V20(GND) U1.V25(GND) U1.W1(GND) U1.W2(GND) U1.W5(GND) U1.W6(GND) U1.W12(GND) U1.W14(GND) U1.W16(GND) U1.W18(GND) U1.W23(GND) U1.W28(GND) U1.Y2(GND) U1.Y3(GND) U1.Y4(GND) U1.Y5(GND) U1.Y11(GND) U1.Y13(GND) U1.Y15(GND) U1.Y21(GND) U1.Y26(GND) ; port Ground  [project net B503_Ground]

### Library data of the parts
J31 = 2007132: Manufacturer: TE Connectivity; Manufacturer Part Number: 2007132-1; Gender: Female; Number of Ports: 4; Data Rate: 16Gbps; PCB Thickness: 2.25mm; Tail Length: 2.05mm
MH1-MH25 = MH_5_3.2: Mounting Holes_5_3.2
U1 = FBVB900: as U1 on sheet XilinxPower

## Sheet Power_Ethernet.SchDoc
size A3
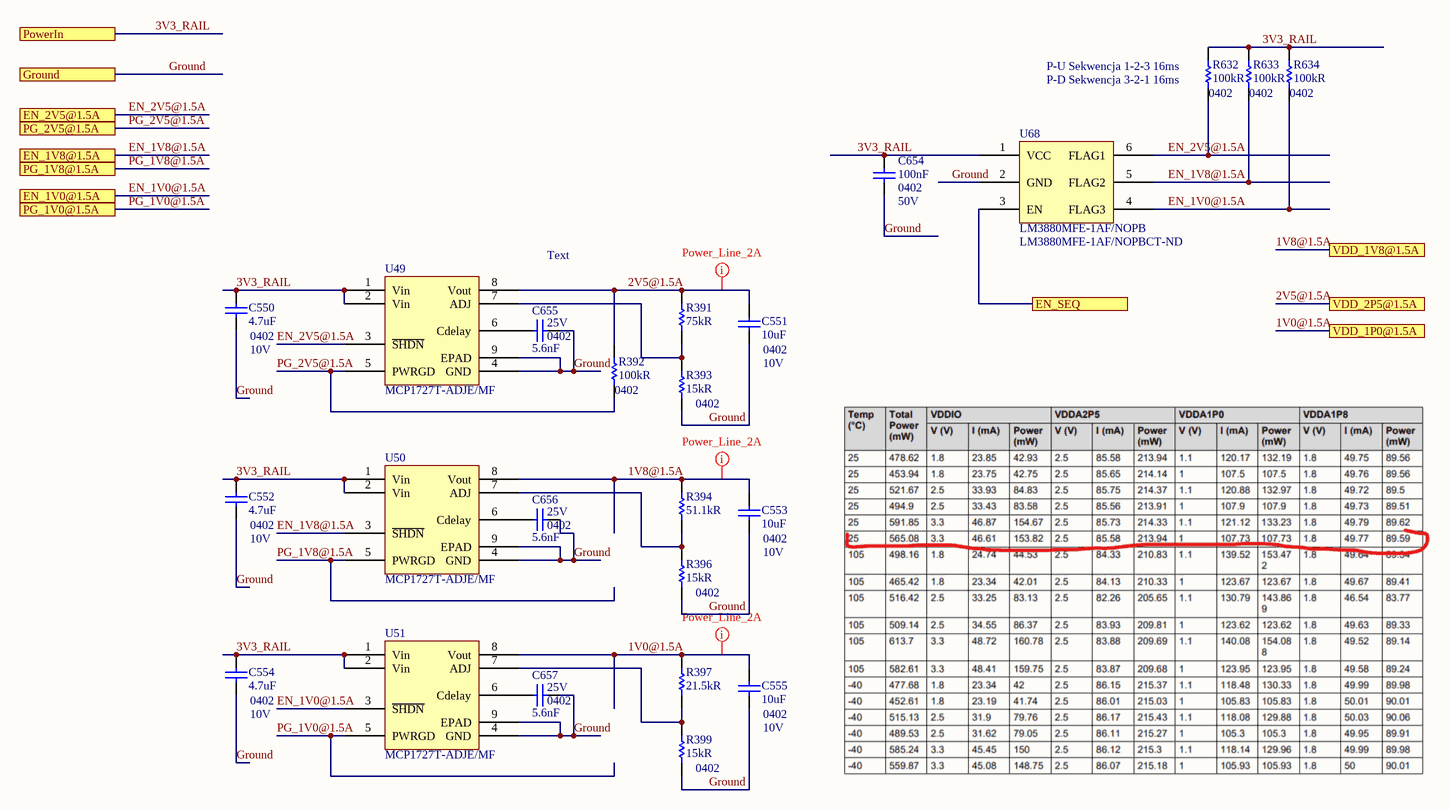
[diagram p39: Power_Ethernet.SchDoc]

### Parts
C550  4.7uF  Case/Package: 0402  Voltage Rating: 10V  [CAP 0402/1005 KK]
C551  10uF  Case/Package: 0402  Voltage Rating: 10V  [CAP 0402/1005 KK]
C552  4.7uF  Case/Package: 0402  Voltage Rating: 10V  [CAP 0402/1005 KK]
C553  10uF  Case/Package: 0402  Voltage Rating: 10V  [CAP 0402/1005 KK]
C554  4.7uF  Case/Package: 0402  Voltage Rating: 10V  [CAP 0402/1005 KK]
C555  10uF  Case/Package: 0402  Voltage Rating: 10V  [CAP 0402/1005 KK]
C654  Case/Package: 0402  Voltage Rating: 50V  [CAP 0402/1005 KK]  (hidden comment: 100nF)
C655  5.6nF  Case/Package: 0402  Voltage Rating: 25V  [CAP 0402/1005 KK]
C656  5.6nF  Case/Package: 0402  Voltage Rating: 25V  [CAP 0402/1005 KK]
C657  5.6nF  Case/Package: 0402  Voltage Rating: 25V  [CAP 0402/1005 KK]
R391  75kR  [RES 0402/1005 RF KK]
R392  100kR  Case/Package: 0402  [RES 0402/1005 RF KK]
R393  15kR  Case Code (Imperial): 0402  [RES 0402/1005 RF KK]
R394  51.1kR  [RES 0402/1005 RF KK]
R396  15kR  Case Code (Imperial): 0402  [RES 0402/1005 RF KK]
R397  21.5kR  [RES 0402/1005 RF KK]
R399  15kR  Case Code (Imperial): 0402  [RES 0402/1005 RF KK]
R632  100kR  Case/Package: 0402  [RES 0402/1005 RF KK]
R633  100kR  Case/Package: 0402  [RES 0402/1005 RF KK]
R634  100kR  Case/Package: 0402  [RES 0402/1005 RF KK]
U49  MCP1727T-ADJE/MF  [MCP1727T-ADJE/MF]
U50  MCP1727T-ADJE/MF  [MCP1727T-ADJE/MF]
U51  MCP1727T-ADJE/MF  [MCP1727T-ADJE/MF]
U68  LM3880MFE-1AF/NOPB  Supplier Part Number 1: LM3880MFE-1AF/NOPBCT-ND  [LM3880-Q1]

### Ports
EN_1V0@1.5A, EN_1V8@1.5A, EN_2V5@1.5A, EN_SEQ, Ground, PG_1V0@1.5A, PG_1V8@1.5A, PG_2V5@1.5A, PowerIn, VDD_1P0@1.5A, VDD_1V8@1.5A, VDD_2P5@1.5A

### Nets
Ground: C550.1 C551.1 C552.1 C553.1 C554.1 C555.1 C654.1 C655.2 C656.2 C657.2 R393.1 R396.1 R399.1 U49.4(GND) U49.9(EPAD) U50.4(GND) U50.9(EPAD) U51.4(GND) U51.9(EPAD) U68.2(GND) ; port Ground  [project net B503_Ground]
1V0@1.5A: C555.2 R397.2 U51.8(Vout) ; port VDD_1P0@1.5A
1V8@1.5A: C553.2 R394.2 U50.8(Vout) ; port VDD_1V8@1.5A
2V5@1.5A: C551.2 R391.2 R392.2 U49.8(Vout) ; port VDD_2P5@1.5A
3V3_RAIL: C550.2 C552.2 C554.2 C654.2 R632.2 R633.2 R634.2 U49.1(Vin) U49.2(Vin) U50.1(Vin) U50.2(Vin) U51.1(Vin) U51.2(Vin) U68.1(VCC) ; port PowerIn
EN_1V0@1.5A: R634.1 U51.3(~{SHDN}) U68.4(FLAG3) ; port EN_1V0@1.5A
EN_1V8@1.5A: R633.1 U50.3(~{SHDN}) U68.5(FLAG2) ; port EN_1V8@1.5A
EN_2V5@1.5A: R632.1 U49.3(~{SHDN}) U68.6(FLAG1) ; port EN_2V5@1.5A
ETH_VDDIO: U68.3(EN) ; port EN_SEQ
PG_1V0@1.5A: U51.5(PWRGD) ; port PG_1V0@1.5A  [project net GPIOa_00.GPIO5]
PG_1V8@1.5A: U50.5(PWRGD) ; port PG_1V8@1.5A  [project net GPIOa_00.GPIO6]
PG_2V5@1.5A: R392.1 U49.5(PWRGD) ; port PG_2V5@1.5A
NetC655_1: C655.1 U49.6(Cdelay)
NetC656_1: C656.1 U50.6(Cdelay)
NetC657_1: C657.1 U51.6(Cdelay)
NetR391_1: R391.1 R393.2 U49.7(ADJ)
NetR394_1: R394.1 R396.2 U50.7(ADJ)
NetR397_1: R397.1 R399.2 U51.7(ADJ)

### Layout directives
net class Power_Line_2A: 1V0@1.5A, 1V8@1.5A, 2V5@1.5A

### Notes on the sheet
- (near R632) P-U Sekwencja 1-2-3 16ms
- (near R632) P-D Sekwencja 3-2-1 16ms
- Text

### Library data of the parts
C550 C552 C554 = Capacitor: as C223 on sheet RAM_Power
C551 C553 C555 = Capacitor: CAP CER 10UF 10V X5R 0402; Manufacturer: Samsung; Manufacturer Part Number: CL05A106MP8NUB8; Tolerance: 20%
C654 = Capacitor: as C219-C222 on sheet RAM_Power
C655-C657 = Capacitor: Manufacturer: Yageo; Manufacturer Part Number: CC0402KRX7R8BB562; Tolerance: 10%; Dielectric: X7R
R391 = Resistor: RES SMD 75K OHM 1% 1/16W 0402; Manufacturer: Yageo; Manufacturer Part Number: RC0402FR-0775KL; Power Rating: 62.5mW; Voltage Rating: 50V; Temperature Coefficient: 100ppm/°C; Max Power Dissipation: 63mW
R392 R632-R634 = Resistor: Manufacturer 1: Panasonic; Manufacturer Part Number 1: ERA-2AED104X; Tolerance: 0.5%; Power Rating: 63mW; Voltage Rating: 25V; Temperature Coefficient: 25ppm/°C
R393 R396 R399 = Resistor: Manufacturer: Panasonic; Manufacturer Part Number: ERJ-2RKF1502X; Tolerance: 1%; Voltage Rating: 50V; Power Rating: 100mW; Temperature Coefficient: 100ppm/°C
R394 = Resistor: RES 51.1K OHM 1% 1/16W 0402; Manufacturer: Stackpole Electronics; Manufacturer Part Number: RMCF0402FT51K1; Power Rating: 63mW; Temperature Coefficient: 100ppm/°C
R397 = Resistor: RES 21.5K OHM 1% 1/16W 0402; Manufacturer: Stackpole Electronics; Manufacturer Part Number: RMCF0402FT21K5; Max Power Dissipation: 63mW; Temperature Coefficient: 100ppm/°C
U49-U51 = MCP1727T-ADJE/MF: IC REG LDO ADJ 1.5A 8DFN; Manufacturer 1: Microchip; Number of Outputs: 1; Min Input Voltage: 2.3V; Max Input Voltage: 6V; Output Voltage: 5V; Dropout Voltage: 330mV; Input Bias Current: 120uA; Reference Voltage: 410mV; Polarity: Positive; Accuracy: 0.5%; Output Type: Adjustable
U68 = LM3880MFE-1AF/NOPB: IC PWR SUPPLY SEQUENCER SOT23-6; Manufacturer: TI National Semiconductor; Min Supply Voltage: 2.7V; Max Supply Voltage: 5.5V; Operating Supply Current: 25uA; Number of Voltages Monitored: 3; Overvoltage Threshold: 1.4V; Undervoltage Threshold: 1V; Watchdog Timer: No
